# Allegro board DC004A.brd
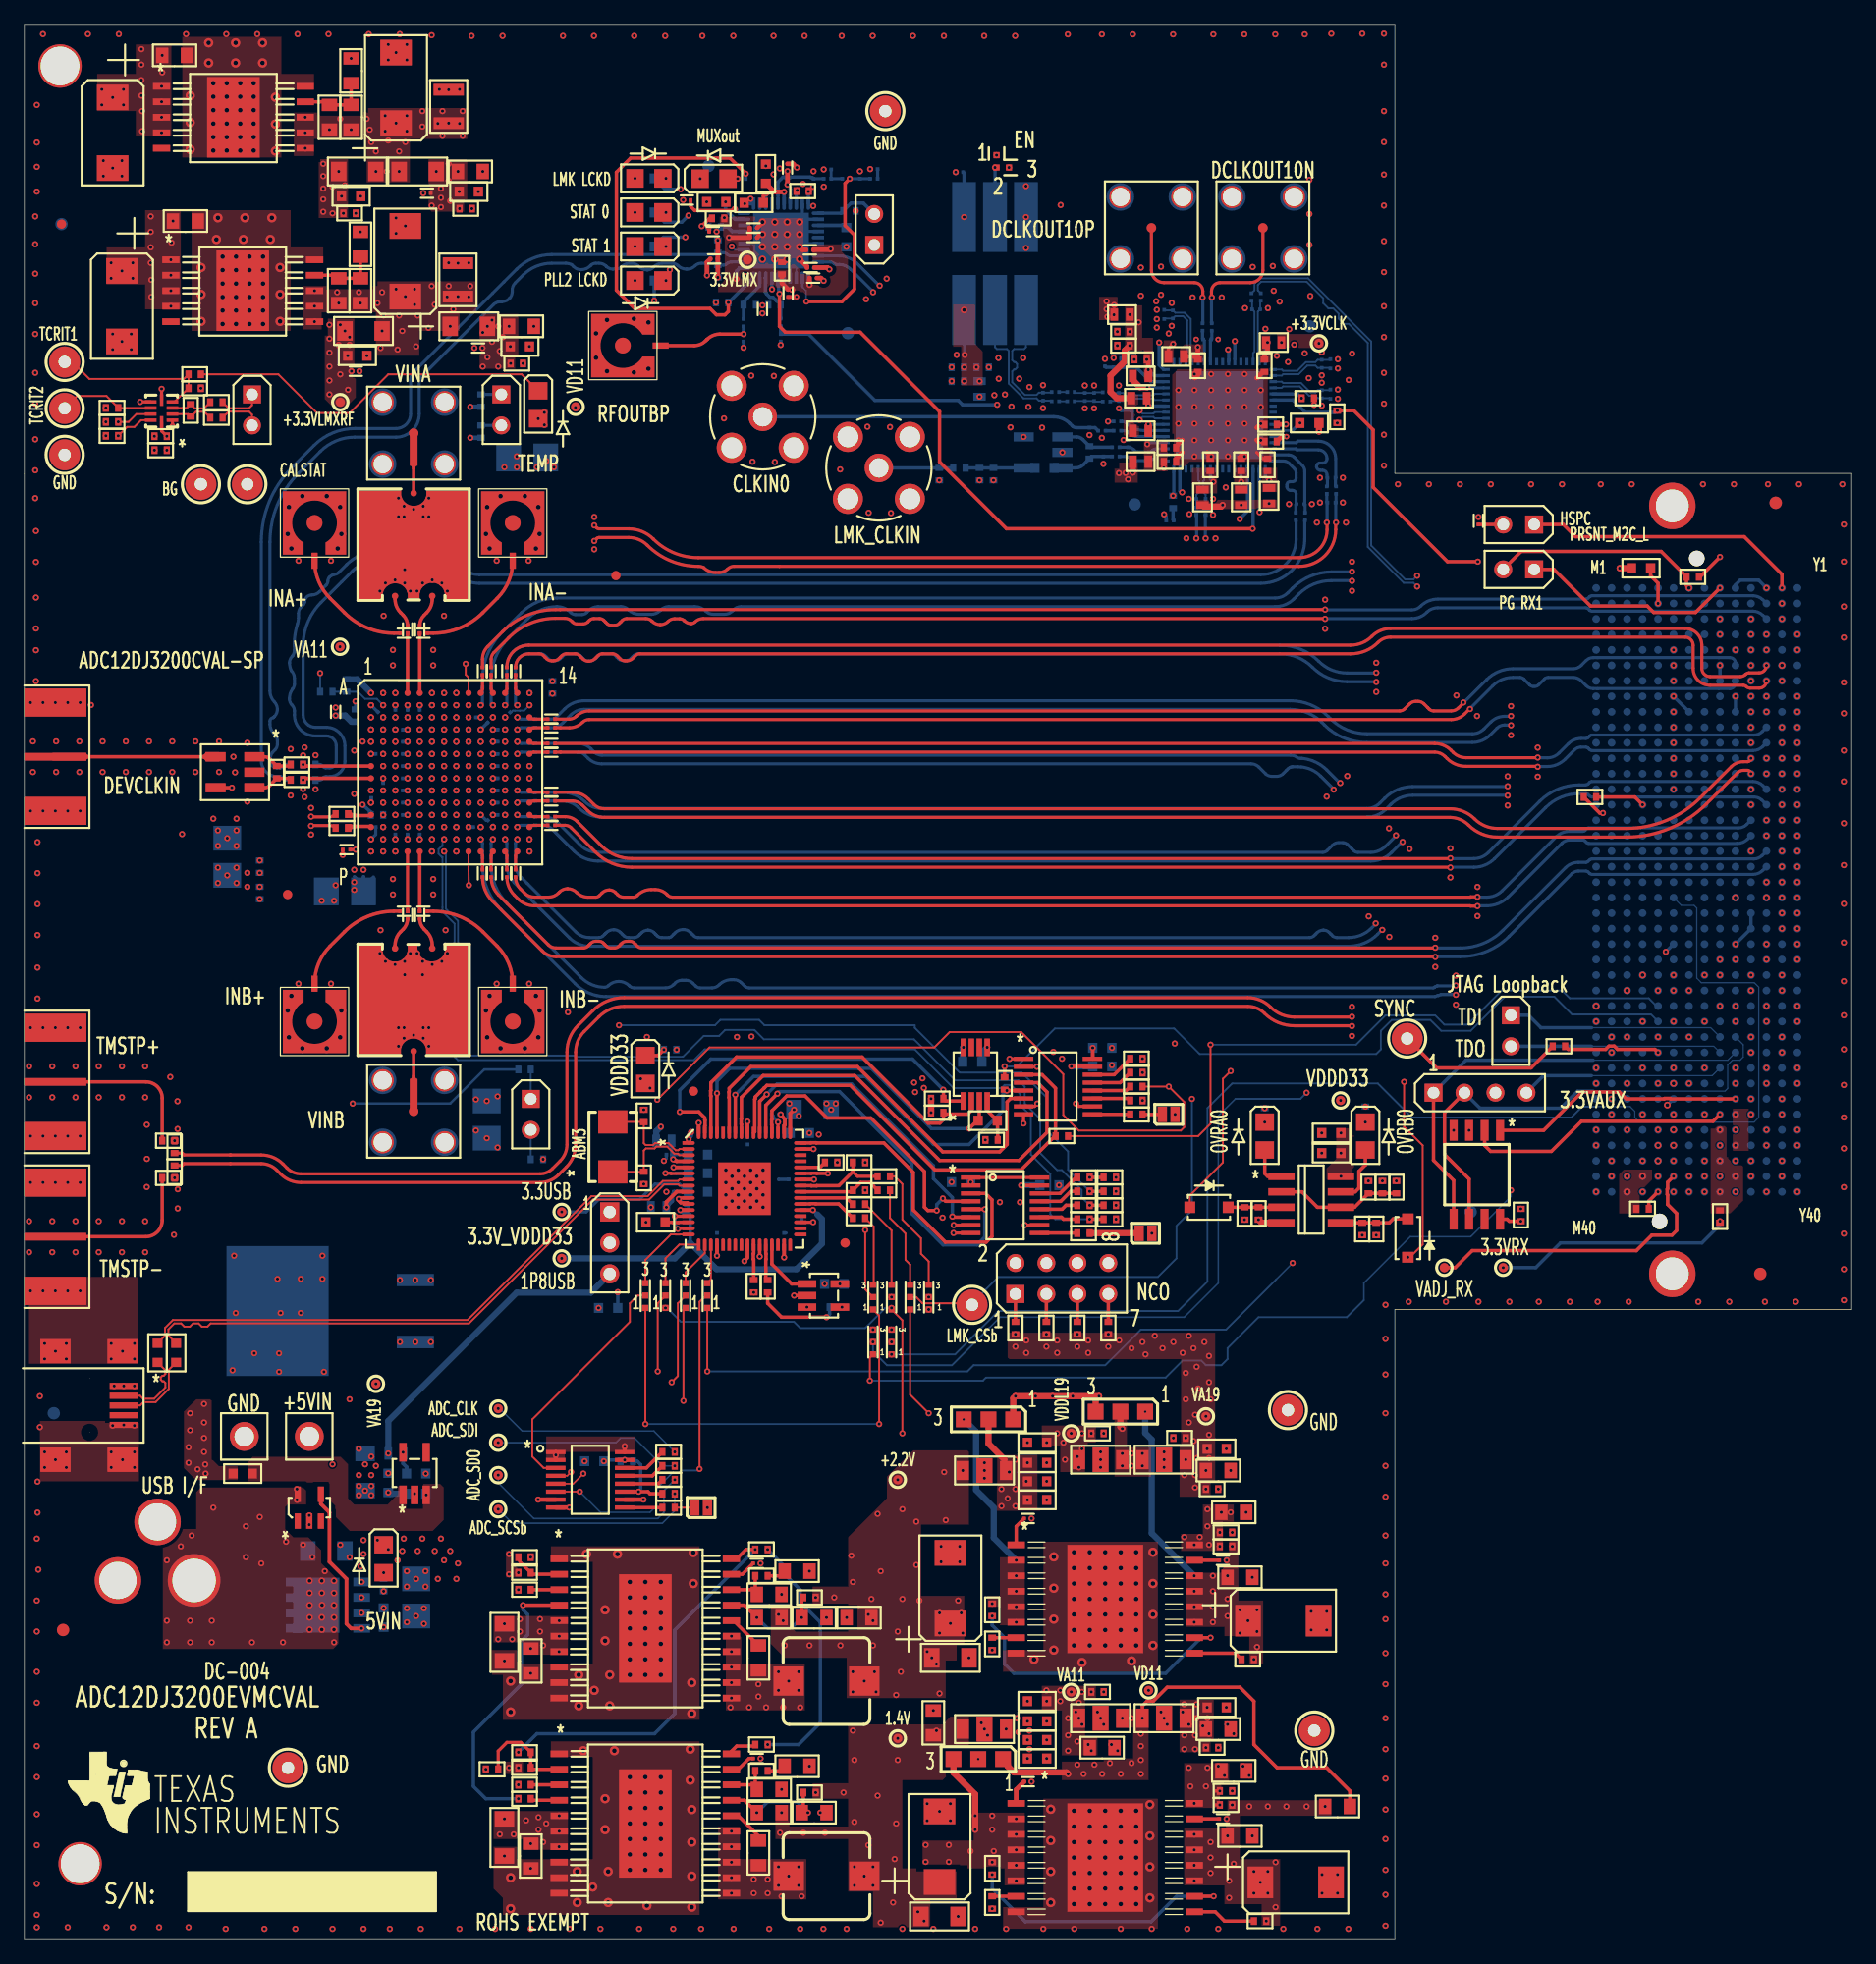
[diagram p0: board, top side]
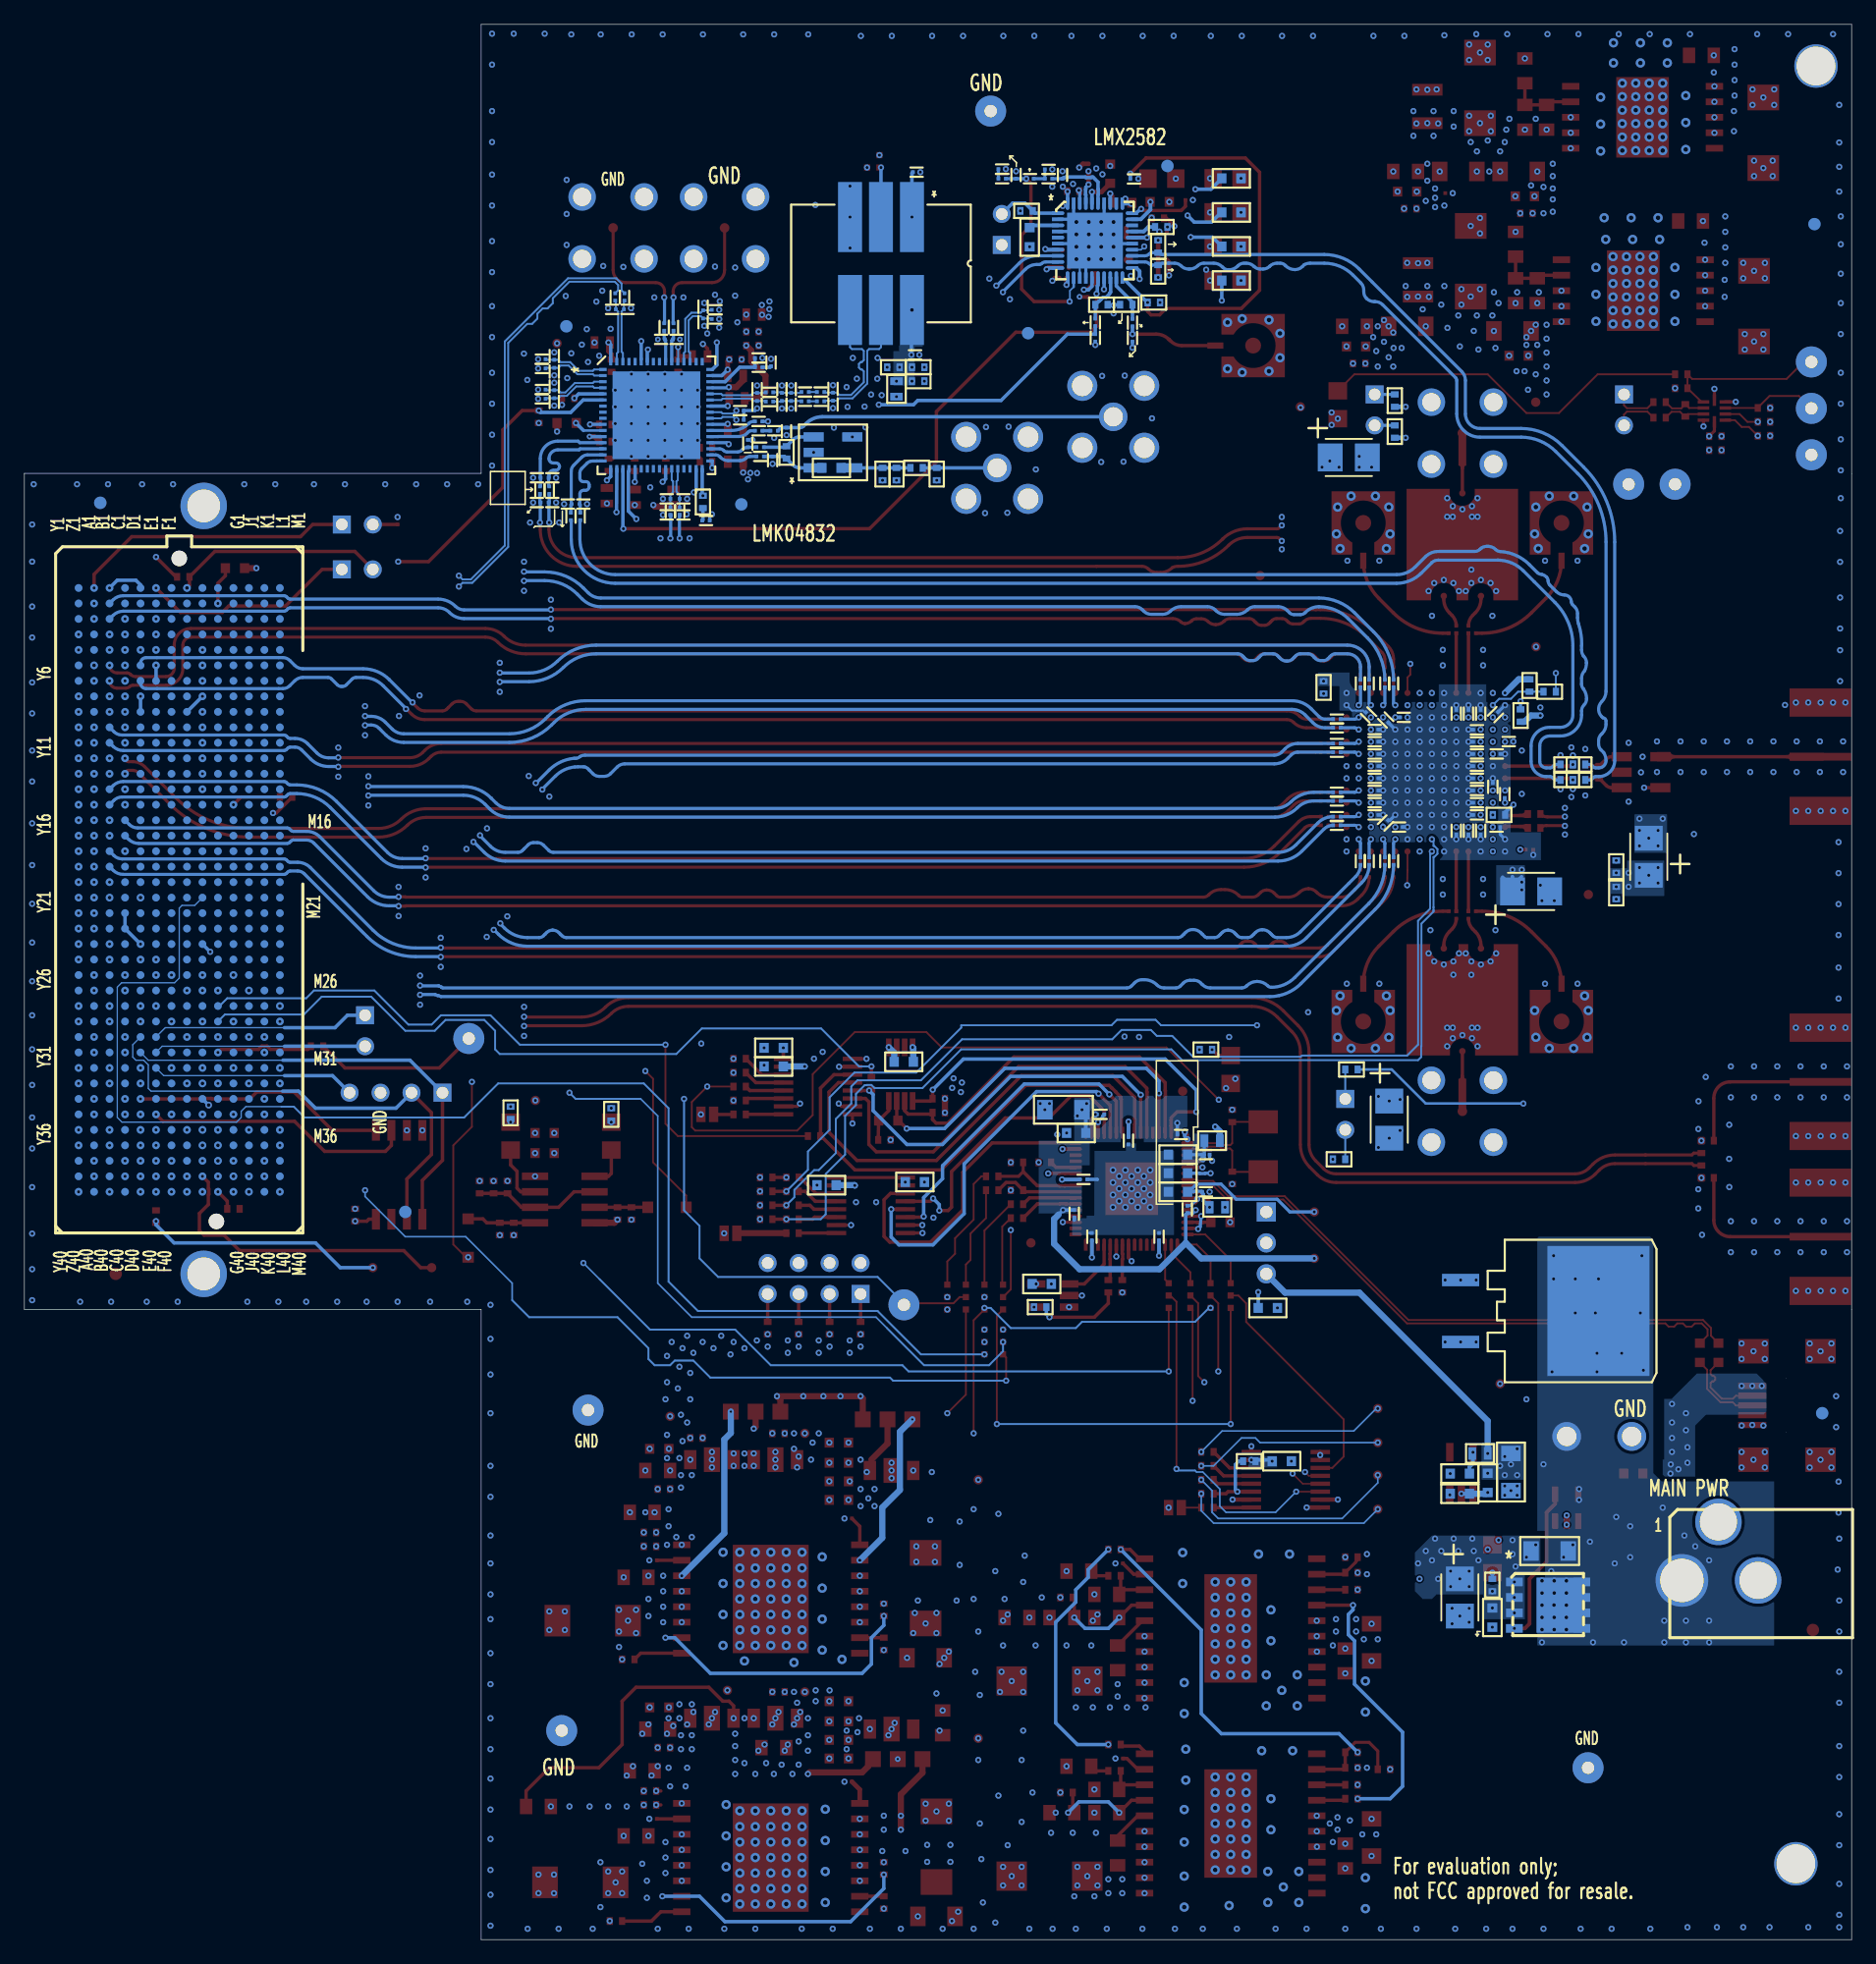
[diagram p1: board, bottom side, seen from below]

Outline 149.86 x 157.1 mm; copper layers: TOP, L02_GND-1, L03_GND-2, L04_SIG-1, L05_GND-3, L06_PWR-1, L07_GND-4, L08_PWR-2, L09_GND-5, L10_SIG-2, L11_GND-6, BOTTOM. Coordinates in mm from the lower left corner of the outline.
Outline path: 0,157.1 0,0 112.39,0 112.39,51.69 149.86,51.69 149.86,120.27 112.39,120.27 112.39,157.1 0,157.1

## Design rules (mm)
net group CLK: nets CLKM CLKP
net group CLKIN0_P_N: nets CLKIN0_N CLKIN0_P
net group CLKIN1: nets CLKIN1_N CLKIN1_P
net group CLKINN: nets CLKINN CLKINP
net group CLKLA0: nets CLKLA_0N CLKLA_0P
net group DA4: nets DA4+ DA4-
net group DA5: nets DA5+ DA5-
net group DA6: nets DA6+ DA6-
net group DA7: nets DA7+ DA7-
net group DB4: nets DB4+ DB4-
net group DB5: nets DB5+ DB5-
net group DB6: nets DB6+ DB6-
net group DB7: nets DB7+ DB7-
net group DCLKOUT2: nets DCLKOUT2_N DCLKOUT2_P
net group DCLKOUT8: nets DCLKOUT8_N DCLKOUT8_P
net group DCLKOUT102: nets DCLKOUT10_N DCLKOUT10_P
net group DIFFPAIR9: nets GTXCLKM GTXCLKP
net group DIFFPAIR10: nets N20382827 N20382847
net group DIFFPAIR11: nets INA+ INA-
net group DMP: nets DM DP
net group DP5: nets SYSREF+ SYSREF-
net group DP8: nets LMX_OSCM LMX_OSCP
net group DP17: nets JESD_SYSREFM JESD_SYSREFP
net group DP19: nets LMX_CLKM LMX_CLKP
net group FPGA_JESD_CLKC: nets FPGA_JESD_CLK_C_N FPGA_JESD_CLK_C_P
net group INAN: nets INAN INAP
net group INBN: nets INBN INBP
net group OSC: nets OSCN OSCP
net group OSC_PAIR: nets OSC_M OSC_P
net group OSCIN: nets OSCINN OSCINP
net group OSCIO: nets OSCI OSCO
net group OSCOUT: nets DCLKOUT6_N DCLKOUT6_P
net group SYNC: nets SYNC_N SYNC_P
net group SYSREF: nets SYSREFM SYSREFP
net group TDIODE: nets TDIODE+ TDIODE-
net group TMSTP: nets TMSTP+ TMSTP-
net group Y2: nets Y1_N Y1_P
net group YO1: nets YO1_N YO1_P
net group A-INPUT: nets CLK+ CLK- CLK_+ CLK_- DEVCLKIN INA_+ INA_- INB+ INB- INB_+ INB_- TMSP+ TMSP- VINA VINB
net group HS: nets DA0+ DA0- DA0_M DA0_P DA1+ DA1- DA1_M DA1_P DA2+ DA2- DA2_M DA2_P DA3+ DA3- DA3_M DA3_P DA4_M DA4_P DA5_M DA5_P DA6_M DA6_P DA7_M DA7_P DB0+ DB0- DB0_M DB0_P DB1+ DB1- DB1_M DB1_P DB2+ DB2- DB2_M DB2_P DB3+ DB3- DB3_M DB3_P DB4_M DB4_P DB5_M DB5_P DB6_M DB6_P DB7_M DB7_P
net group LENGTH: nets FPGA_JESD_CLK_A_N FPGA_JESD_CLK_A_P FPGA_JESD_CLK_B_N FPGA_JESD_CLK_B_P FPGA_JESD_SYSREFM FPGA_JESD_SYSREFP

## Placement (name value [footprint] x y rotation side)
BALUN1  BALUN, HIGH POWER, SMT  [BALUN_320X320_MARKI_0006SMG]  31.93 114.43 0 top
BALUN2  BALUN, HIGH POWER, SMT  [BALUN_320X320_MARKI_0006SMG]  31.93 77.09 180 top
C1  0.1uF  [0603]  107.19 66.17 180 top
C2  1uF  [0603]  107.19 64.52 180 top
C3  .1uF  [0402]  101.22 59.56 90 top
C4  .1uF  [0402]  111.38 61.72 270 top
C5  .1uF  [0201]  43.22 98.11 0 top
C6  .1uF  [0201]  43.22 97.4 0 top
C7  .1uF  [0201]  43.22 100.11 0 top
C8  .1uF  [0201]  43.22 99.4 0 top
C9  .1uF  [0201]  39.57 104.05 90 top
C10  .1uF  [0201]  40.28 104.05 90 top
C11  .1uF  [0201]  37.57 104.05 90 top
C12  .1uF  [0201]  38.28 104.05 90 top
C13  .1uF  [0201]  42.22 98.11 0 bottom
C14  .1uF  [0402]  109.73 58.29 90 top
C15  .1uF  [0201]  42.22 97.4 0 bottom
C16  .1uF  [0201]  42.22 100.11 0 bottom
C17  10uF  [0603]  83.06 17.91 0 top
C18  .1uF  [0201]  42.22 99.4 0 bottom
C19  .1uF  [0201]  39.57 103.03 90 bottom
C20  .1uF  [0201]  89.64 123.77 0 bottom
C21  .1uF  [0201]  40.28 103.03 90 bottom
C22  .1uF  [0201]  37.57 103.03 90 bottom
C23  .1uF  [0201]  38.28 103.03 90 bottom
C24  .1uF  [0201]  89.64 124.53 0 bottom
C25  .1uF  [0201]  43.22 93.4 0 top
C26  .1uF  [0201]  43.22 94.11 0 top
C27  .1uF  [0201]  43.22 91.4 0 top
C28  .1uF  [0201]  43.22 92.11 0 top
C29  .1uF  [0201]  39.57 87.46 270 top
C30  .1uF  [0201]  40.28 87.46 270 top
C31  .1uF  [0201]  37.57 87.46 270 top
C32  .1uF  [0201]  38.28 87.46 270 top
C33  .1uF  [0201]  42.22 93.4 0 bottom
C34  .1uF  [0201]  42.22 94.11 0 bottom
C35  .1uF  [0201]  42.22 91.4 0 bottom
C36  .1uF  [0201]  42.22 92.11 0 bottom
C37  .1uF  [0201]  39.57 88.46 270 bottom
C38  .1uF  [0201]  40.28 88.46 270 bottom
C39  .1uF  [0201]  37.57 88.46 270 bottom
C40  .1uF  [0201]  38.28 88.46 270 bottom
C41  100pF  [0402]  11.18 123.32 180 top
C42  .1uF  [0402]  11.18 122.17 180 top
C43  10uF  [TANT_B]  41.24 121.57 180 bottom
C44  100pF  [0402]  13.64 125.44 90 top
C45  .1uF  [0402]  26.04 92.33 0 top
C47  .1uF  [0402]  26.04 91.19 0 top
C48  4700pF  [0402]  23.37 96.39 180 bottom
C49  4700pF  [0402]  22.35 96.39 0 top
C50  4700pF  [0402]  22.35 96.39 0 bottom
C51  4700pF  [0402]  22.35 95.12 0 bottom
C52  4700pF  [0402]  22.35 95.13 0 top
C53  4700pF  [0402]  23.37 95.12 180 bottom
C54  .1uF  [0201]  30.73 99.24 0 bottom
C55  .1uF  [0201]  30.73 98.25 0 bottom
C56  .1uF  [0201]  30.73 97.26 0 bottom
C57  .1uF  [0201]  29.11 97.26 180 bottom
C58  .1uF  [0201]  29.42 94.56 90 bottom
C59  .1uF  [0201]  30.73 96.26 0 bottom
C60  .1uF  [0201]  30.73 92.26 0 bottom
C61  .1uF  [0201]  30.73 93.26 0 bottom
C62  .1uF  [0201]  30.73 95.26 0 bottom
C63  .1uF  [0201]  30.73 94.26 0 bottom
C64  .1uF  [0201]  39.12 93.26 180 bottom
C65  .1uF  [0201]  39.12 94.26 180 bottom
C66  1uF  [0402]  19.3 85.85 270 bottom
C67  1uF  [0402]  19.3 88.01 90 bottom
C68  10uF  [TANT_B]  16.64 88.82 90 bottom
C69  .1uF  [0201]  29.21 100.48 135 bottom
C70  .1uF  [0201]  28.45 93.95 90 bottom
C71  .1uF  [0201]  29.12 91.26 180 bottom
C72  .1uF  [0201]  28.12 98.27 180 bottom
C73  .1uF  [0201]  32.43 100.56 90 bottom
C74  .1uF  [0201]  31.43 100.56 90 bottom
C75  .1uF  [0201]  30.43 100.56 90 bottom
C76  .1uF  [0201]  25.53 100.71 90 top
C77  .1uF  [0201]  26.42 89.41 180 top
C78  .1uF  [0201]  32.43 90.95 270 bottom
C79  .1uF  [0201]  31.43 90.95 270 bottom
C80  .1uF  [0201]  30.43 90.95 270 bottom
C81  1uF  [0402]  27.15 100.41 90 bottom
C82  1uF  [0402]  28.92 92.26 180 bottom
C83  10uF  [TANT_B]  26.29 85.98 180 bottom
C84  .1uF  [0201]  36.73 100.26 180 bottom
C85  .1uF  [0201]  39.12 99.26 180 bottom
C86  .1uF  [0201]  39.12 98.26 180 bottom
C87  .1uF  [0201]  39.12 97.25 180 bottom
C88  .1uF  [0201]  39.12 96.26 180 bottom
C89  .1uF  [0201]  38.21 100.04 225 bottom
C90  .1uF  [0201]  39.62 100.46 45 bottom
C91  .1uF  [0201]  37.12 91.26 180 bottom
C92  .1uF  [0201]  39.12 92.26 180 bottom
C93  .1uF  [0201]  38.23 91.59 135 bottom
C94  1uF  [0402]  43.31 102.72 90 bottom
C95  10uF  [TANT_B]  37.92 67.26 270 bottom
C96  .1uF  [0201]  39.12 95.26 180 bottom
C99  100pF  [0201]  56.57 137.87 180 top
C100  .1uF  [0201]  64.42 138.6 180 top
C101  .1uF  [0201]  59.79 139.61 0 top
C102  1uF  [0402]  62.13 137.1 270 top
C103  .1uF  [0201]  64.7 136.29 0 top
C104  .1uF  [0201]  64.49 137.15 0 top
C105  100pF  [0201]  60.53 133.75 270 top
C106  .1uF  [0201]  62.64 135.05 270 top
C107  .1uF  [0201]  62.59 145.36 270 top
C108  100pF  [0201]  62.03 132.66 270 bottom
C109  .1uF  [0201]  56.47 140.1 180 top
C110  100pF  [0201]  58.98 132.63 270 bottom
C111  1uF  [0402]  56.62 140.48 0 bottom
C112  10uF  [0603]  56.75 142.54 0 top
C113  .1uF  [0201]  59.79 140.41 0 top
C114  1uF  [0402]  56.9 141.19 0 top
C115  10uF  [0603]  60.81 144.85 270 top
C116  10uF  [0603]  67.41 139.64 90 bottom
C117  1uF  [0402]  63.83 143.43 180 top
C118  10uF  [0603]  59.82 142.46 0 top
C119  560pF  [0201]  68.53 144.75 90 bottom
C120  .047uF  [0201]  69.67 144.44 0 bottom
C121  6800pF  [0201]  65.86 145.2 180 bottom
C122  6800pF  [0201]  64.72 144.75 90 bottom
C123  10uF  [0603]  83.06 16.38 0 top
C124  10uF  [0603]  83.06 39.12 0 top
C125  10uF  [0603]  83.06 37.59 0 top
C126  10uF  [0603]  83.06 36.07 0 top
C127  .1uF  [0805]  99.7 29.72 0 top
C128  .68uF  [0402]  94.21 117.93 270 bottom
C129  10uF  [0603]  83.06 14.86 0 top
C130  .1uF  [0201]  76.68 144.98 180 bottom
C131  3900pF  [0201]  89.64 128.98 180 bottom
C132  47pF  [0201]  89.64 129.74 180 bottom
C133  .1uF  [0201]  105.04 116.74 270 bottom
C134  .01uF  [0201]  89.51 121.66 0 bottom
C135  .1uF  [0201]  104.27 116.74 270 bottom
C136  .01uF  [0201]  89.51 122.42 0 bottom
C137  .1uF  [0201]  90.53 122.71 270 bottom
C138  .1uF  [0201]  76.81 129.99 0 bottom
C139  100pF  [0402]  76.56 128.98 0 bottom
C140  2200pF  [0402]  78.59 128.98 180 bottom
C141  10pF  [0402]  76.56 127.83 0 bottom
C142  .1uF  [0201]  96.62 132.28 90 bottom
C143  .1uF  [0201]  97.39 132.28 90 bottom
C144  .1uF  [0201]  85.83 126.18 0 bottom
C145  .1uF  [0201]  88.75 126.16 0 bottom
C146  .1uF  [0201]  89.77 125.9 90 bottom
C149  .1uF  [0201]  85.83 126.94 0 bottom
C150  .1uF  [0201]  88.75 126.92 0 bottom
C151  .1uF  [0201]  96.88 117.16 270 bottom
C152  12pF  [0201]  89.77 127.17 270 bottom
C153  .1uF  [0201]  96.12 117.16 270 bottom
C154  1uF  [0402]  102.21 124.28 0 top
C155  .1uF  [0402]  93.96 121.23 180 top
C156  0.01uF  [0402]  93.96 122.37 180 top
C157  1uF  [0402]  101.96 120.97 90 top
C158  1uF  [0402]  99.8 120.97 90 top
C159  1uF  [0402]  97.26 120.97 90 top
C160  1uF  [0402]  90.15 131.9 0 top
C161  .1uF  [0402]  90.15 130.75 0 top
C162  0.01uF  [0402]  91.54 129.61 0 top
C163  .1uF  [0402]  102.21 122.88 180 top
C164  10uF  [0603]  105.39 124.4 0 top
C165  1uF  [0402]  96.24 129.1 270 top
C166  1uF  [0402]  101.7 129.1 270 top
C167  1uF  [0402]  122.73 59.44 270 top
C168  10uF  [0603]  55.25 64.39 0 bottom
C169  .1uF  [0201]  52.96 64.39 180 bottom
C170  10uF  [0603]  55.25 61.34 0 bottom
C171  .1uF  [0201]  52.96 61.34 180 bottom
C172  0.1uF  [0603]  66.42 53.78 180 bottom
C173  1uF  [0603]  32.13 38.23 0 bottom
C174  100uF  [1206]  27.94 38.35 270 bottom
C175  1uF  [0603]  32.13 36.58 180 bottom
C176  .1uF  [0201]  61.6 67.69 180 bottom
C177  0.1uF  [0603]  29.84 37.47 270 bottom
C178  100uF  [1206]  64.64 68.07 0 bottom
C179  10uF  [0603]  63.6 66.17 0 bottom
C180  1uF  [0603]  77.74 72 0 bottom
C181  .1uF  [0201]  54.99 66.04 180 bottom
C182  .1uF  [0201]  54.48 59.89 90 bottom
C183  .1uF  [0201]  63.75 59.54 270 bottom
C184  18pF  [0402]  50.8 67.56 90 top
C185  18pF  [0402]  50.8 62.48 270 top
C186  .1uF  [0201]  56.8 57.66 90 bottom
C187  .1uF  [0201]  62.99 62.36 180 bottom
C188  .1uF  [0201]  62.31 57.66 90 bottom
C189  .1uF  [0201]  59.31 65.53 270 bottom
C190  0.1uF  [0603]  47.88 51.82 180 bottom
C191  0.1uF  [0603]  46.74 39.24 180 bottom
C192  0.1uF  [0603]  76.83 62.14 180 bottom
C193  0.1uF  [0603]  84.07 61.89 0 bottom
C194  0.1uF  [0603]  88.4 73.15 0 bottom
C195  0.1uF  [0603]  88.4 71.62 0 bottom
C196  47uF  [TANT_B]  32.13 28.07 270 bottom
C198  10uF  [0603]  29.46 26.42 270 bottom
C200  10uF  [0603]  83.06 40.77 180 top
C201  1uF  [0402]  88.01 41.53 0 top
C202  10uF  [0603]  97.79 40.26 0 top
C203  .1uF  [0402]  94.74 41.15 180 top
C204  33uF  [0805]  97.92 38.48 0 top
C205  1uF  [0402]  97.41 36.96 0 top
C206  220uF  [TANT_D]  103.25 26.16 0 top
C207  1000pF  [0805]  99.19 35.05 0 top
C208  330uF  [TANT_D]  75.95 28.83 90 top
C209  .1uF  [0805]  68.45 26.42 180 top
C210  10000pF  [0201]  98.3 31.11 0 top
C211  2200pF  [0201]  82.3 34.54 0 top
C212  47uF  [1206]  75.95 23.11 0 top
C213  22uF  [1206]  39.37 24.38 270 top
C214  10uF  [0805]  41.53 22.86 270 top
C215  12nF  [0201]  60.07 30.86 0 top
C216  91pF  [0805]  61.09 28.32 0 top
C217  270pF  [0805]  61.09 26.42 180 top
C218  33uF  [0805]  88.39 15.75 0 top
C219  10uF  [0603]  83.06 19.56 180 top
C220  1uF  [0402]  88.01 20.32 0 top
C221  .1uF  [0805]  60.2 23.11 270 top
C222  33uF  [0805]  97.92 17.27 0 top
C223  10uF  [0603]  97.79 19.05 0 top
C224  1uF  [0402]  97.41 15.75 0 top
C225  .027uF  [0805]  63.37 30.23 0 top
C226  1000pF  [0805]  99.19 13.84 0 top
C227  330uF  [TANT_D]  75.06 7.62 90 top
C228  220uF  [TANT_D]  104.27 4.7 0 top
C229  33uF  [0805]  36.58 145.03 0 top
C230  10uF  [0603]  36.45 143.38 0 top
C231  .1uF  [0805]  99.7 8.51 0 top
C232  .1uF  [0805]  74.55 17.78 90 top
C233  .1uF  [0402]  36.2 141.99 0 top
C234  .01uF  [0201]  33.02 143.26 180 top
C236  10uF  [0603]  26.8 143 0 top
C237  .1uF  [0402]  26.67 141.61 0 top
C242  33uF  [0805]  40.77 132.33 0 top
C243  10uF  [0603]  40.64 130.68 0 top
C244  .1uF  [0402]  40.39 129.29 0 top
C245  .01uF  [0201]  37.21 130.56 180 top
C247  10uF  [0603]  27.3 129.92 0 top
C248  .01uF  [0201]  27.18 128.65 0 top
C249  .1uF  [0201]  97.18 116.86 0 bottom
C250  .1uF  [0201]  95.81 116.86 180 bottom
C251  .1uF  [0805]  60.2 7.11 270 top
C254  270pF  [0805]  61.09 10.41 180 top
C255  22uF  [1206]  39.37 8.38 270 top
C256  10uF  [0805]  41.53 6.86 270 top
C258  12nF  [0201]  60.07 14.86 0 top
C259  1uF  [0805]  12.32 154.56 0 top
C260  15uF  [TANT_X]  7.24 148.21 270 top
C261  470pF  [0805]  25.02 149.48 90 top
C262  22uF  [TANT_D]  30.48 151.89 90 top
C263  .1uF  [1210]  34.8 150.37 90 top
C264  1uF  [0805]  13.21 140.97 0 top
C265  15uF  [TANT_X]  8 133.99 270 top
C266  470pF  [0805]  25.78 135.26 90 top
C267  22uF  [TANT_D]  31.24 137.67 90 top
C268  .1uF  [1210]  35.56 136.14 90 top
C269  .027uF  [0805]  63.37 14.22 0 top
C270  47uF  [1206]  75.06 1.91 0 top
C271  150pF  [0805]  61.09 12.32 0 top
C272  2200pF  [0201]  82.3 12.95 0 top
C273  10000pF  [0201]  98.3 9.91 0 top
D1  LED RED  [LED_0805]  42.14 125.9 90 top
D2  LED GREEN  [LED_0805]  56.57 144.44 180 top
D3  LED GREEN  [LED_0805]  51.22 141.68 0 top
D4  LED GREEN  [LED_0805]  51.22 138.88 0 top
D5  LED GREEN  [LED_0805]  51.22 144.47 0 top
D6  LED GREEN  [LED_0805]  51.22 136.09 0 top
D7  LED GREEN  [LED_0805]  50.93 71.37 90 top
D8  LED GREEN  [LED_0805]  29.46 31.24 90 top
D9  1N4148W  [DIODE_SM_1N4148W]  113.46 57.55 90 top
D10  LED ORANGE  [LED_0805]  109.98 65.91 90 top
D11  LED ORANGE  [LED_0805]  101.73 65.91 90 top
D12  1N4148W  [DIODE_SM_1N4148W]  97.16 60.07 0 top
D13  MBRB2515L  [DIODE_MBRB2515L]  26.42 51.56 0 bottom
F1  FUSE 10A 63V FAST  [1206]  24.77 31.88 0 bottom
FB1  120 OHM @ 100MHz  [IND_0603]  78.34 127.2 270 bottom
FB2  120 OHM @ 100MHz  [IND_0603]  91.54 121.23 0 top
FB3  120 OHM @ 100MHz  [IND_0603]  102.08 118.43 90 top
FB4  120 OHM @ 100MHz  [IND_0603]  99.8 118.31 90 top
FB5  120 OHM @ 100MHz  [IND_0603]  96.62 118.31 90 top
FB6  120 OHM @ 100MHz  [IND_0603]  90.02 133.29 0 top
FB7  120 OHM @ 100MHz  [IND_0603]  91.54 123.77 0 top
FB8  120 OHM @ 100MHz  [IND_0603]  91.42 126.44 0 top
FB9  120 OHM @ 100MHz  [IND_0603]  91.54 128.26 180 top
FB10  120 OHM @ 100MHz  [IND_0603]  94.46 129.86 0 top
FB11  120 OHM @ 100MHz  [IND_0603]  102.47 131.01 180 top
FB12  120 OHM @ 100MHz  [IND_0603]  52.45 65.53 0 bottom
FB13  120 OHM @ 100MHz  [IND_0603]  52.02 60.07 0 bottom
FB14  26 OHM @ 100MHz  [IND_0603]  30.48 39.88 180 bottom
FB16  27uF  [1206_BEAD_NFM31P]  88.27 39.37 180 top
FB17  27uF  [1206_BEAD_NFM31P]  93.47 39.37 0 top
FB18  27uF  [1206_BEAD_NFM31P]  88.27 18.16 180 top
FB19  27uF  [1206_BEAD_NFM31P]  93.47 18.16 0 top
FB20  120 OHM @ 100MHz  [1206]  32.26 145.03 0 top
FB21  120 OHM @ 100MHz  [1206]  27.3 145.03 180 top
FB22  120 OHM @ 100MHz  [1206]  36.45 132.33 0 top
FB23  120 OHM @ 100MHz  [1206]  27.81 131.95 180 top
FB24  27uF  [1206_BEAD_NFM31P]  78.74 38.48 0 top
FB25  27uF  [1206_BEAD_NFM31P]  78.74 17.27 0 top
J1  SMP, PCB, SMT  [SMP_B120]  23.8 116.2 0 top
J2  SMA, THVT, SMT CENTER PIN  [SMA_THVT_SMT_250X250]  31.93 123.57 90 top
J3  SMP, PCB, SMT  [SMP_B120]  40.05 116.2 0 top
J4  SMP, PCB, SMT  [SMP_B120]  23.8 75.31 180 top
J5  SMA, THVT, SMT CENTER PIN  [SMA_THVT_SMT_250X250]  31.93 67.95 270 top
J6  SMP, PCB, SMT  [SMP_B120]  40.05 75.31 180 top
J7  HDR, THVT, 8POS, .100, GOLD  [HDR_THVT_2X4_100_M]  81.28 52.96 90 top
J8  HDR, THVT, 2POS, .100, GOLD  [HDR_THVT_1X2_100_M]  41.53 68.96 0 top
J9  HDR, THVT, 2POS, .100, GOLD  [HDR_THVT_1X2_100_M]  39.12 126.75 0 top
J14  SMA, JACK, 50 OHM, EDGE MNT  [SMA_SMEL_373X312]  0 70.36 90 top
J15  SMA, JACK, 50 OHM, EDGE MNT  [SMA_SMEL_373X312]  0 57.66 90 top
J17  HDR, THVT, 2POS, .100, GOLD  [HDR_THVT_1X2_100_M]  18.67 126.75 0 top
J18  SMA, JACK, 50 OHM, EDGE MNT  [SMA_SMEL_373X312]  0 97.03 90 top
J20  SMP, PCB, SMT  [SMP_B120]  49.08 130.75 90 top
J22  SMA_THVT_REC  [SMA_THVT_312X312]  70.08 120.72 0 top
J23  SMA, THVT, SMT CENTER PIN  [SMA_THVT_SMT_250X250]  92.43 140.41 0 top
J24  SMA, THVT, SMT CENTER PIN  [SMA_THVT_SMT_250X250]  101.58 140.41 0 top
J25  CON, SMVT, HS, FIELD ARRAY, FMC, MALE  [CON_SMVT_40X14_50_M_MTG]  137.16 86.11 90 bottom
J26  HDR, THVT, 2POS, .100, GOLD  [HDR_THVT_1X2_100_M]  123.83 112.39 270 top
J27  HDR, THVT, 2POS, .100, GOLD  [HDR_THVT_1X2_100_M]  121.92 75.82 0 top
J28  HDR, THVT, 4POS, .100, GOLD  [HDR_THVT_1X4_100_M]  115.57 69.47 90 top
J30  HDR, THVT, 2POS, .100, GOLD  [HDR_THVT_1X2_100_M]  123.83 116.08 270 top
J31  CON, USB, MINI, AB, SMT  [CON_SMRT_USBMNE20_F]  4.7 43.81 0 top
J37  CONN, JACK, PWR, MINI, R/A, TH  [CON_RAPC722_JACK_THVT_3]  10.79 29.46 90 bottom
J38  SMA_THVT_REC  [SMA_THVT_312X312]  60.56 124.91 0 top
JP5  HDR, THVT, 2POS, .100, GOLD  [HDR_THVT_1X2_100_M]  69.7 139.01 180 top
JP6  HDR, THVT, 3POS, .100, GOLD  [HDR_THVT_1X3_100_M]  48.01 59.69 0 top
L6  1.5uH  [IND_SM_6P7MMX6P7MM]  65.79 5.21 0 top
L7  1.5uH  [IND_SM_6P7MMX6P7MM]  65.79 21.21 0 top
MT1  STANDOFF, FEMALE, 4-40 X 1 3/16", AL  [MFG125_PLATED]  4.57 6.22 0 top
MT2  STANDOFF, FEMALE, 4-40 X 1 3/16", AL  [MFG125_PLATED]  2.92 153.68 0 top
NOREF  -  [unnamed]  143.64 117.86 0 top
NOREF#2  -  [#2]  142.88 89.28 270 top
NOREF#3  -  [#2]  141.6 95.63 0 top
NOREF#4  -  [#2]  22.86 95.76 90 top
NOREF#5  -  [#2]  142.88 99.44 270 top
NOREF#6  -  [#2]  41.18 114.88 90 top
NOREF#7  -  [#2]  117.41 77.88 90 top
NOREF#8  -  [#2]  101.58 140.41 0 top
NOREF#9  -  [#2]  10.41 102.11 0 top
NOREF#10  -  [#2]  69.88 135.4 45 top
NOREF#11  -  [#2]  92.43 140.41 0 top
NOREF#12  -  [unnamed]  142.37 54.61 0 top
NOREF#13  -  [#2]  25.42 92.54 90 top
NOREF#14  -  [#2]  96.5 114.94 0 top
NOREF#15  -  [#2]  119.17 85.16 90 top
NOREF#16  -  [#2]  149.86 51.69 90 top
NOREF#17  -  [#2]  106.68 108.72 90 top
NOREF#18  -  [unnamed#3]  48.51 111.89 0 top
NOREF#19  -  [#2]  2.54 57.66 0 top
NOREF#20  -  [#2]  118.29 101.21 135 top
NOREF#21  -  [#2]  145.41 89.28 0 top
NOREF#22  -  [#2]  144.15 91.82 0 top
NOREF#23  -  [#2]  110.87 103.54 90 top
NOREF#24  -  [#2]  141.6 100.71 0 top
NOREF#25  -  [#2]  238.12 63.12 0 top
NOREF#26  -  [#2]  112.39 120.27 90 top
NOREF#27  -  [#2]  140.34 104.52 270 top
NOREF#28  -  [#2]  107.19 116.24 0 top
NOREF#29  -  [#2]  14.07 111.65 0 top
NOREF#30  -  [#2]  142.88 103.25 0 top
NOREF#31  -  [#2]  121.65 94.22 90 top
NOREF#32  -  [#2]  108.88 111.83 90 top
NOREF#33  -  [#2]  141.6 91.82 270 top
NOREF#34  -  [#2]  142.88 109.6 270 top
NOREF#35  -  [#2]  145.41 94.36 0 top
NOREF#36  -  [#2]  0 0 90 top
NOREF#37  -  [#2]  112.39 0 90 top
NOREF#38  -  [#2]  0 157.1 0 top
NOREF#39  -  [#2]  70.08 120.72 0 top
NOREF#40  -  [#2]  145.41 93.09 0 top
NOREF#41  -  [unnamed#3]  54.86 69.6 0 top
NOREF#42  -  [#2]  115.71 80.99 90 top
NOREF#43  -  [unnamed]  3.17 25.4 0 top
NOREF#44  -  [#2]  60.56 124.91 0 top
NOREF#45  -  [#2]  121.92 99.99 90 top
NOREF#46  -  [#2]  142.88 94.36 270 top
NOREF#47  -  [#2]  36.12 99.36 0 top
NOREF#48  -  [#2]  145.41 99.44 0 top
NOREF#49  -  [#2]  3.57 8.72 0 top
NOREF#50  -  [#2]  141.6 101.98 0 top
NOREF#51  -  [#2]  144.15 90.55 0 top
NOREF#52  -  [#2]  6.45 2.98 0 top
NOREF#53  -  [#2]  111.1 83.09 135 top
NOREF#54  -  [#2]  145.41 84.2 0 top
NOREF#55  -  [unnamed#3]  21.59 85.72 0 top
NOREF#56  -  [#2]  -99.82 376.96 0 top
NOREF#57  -  [#2]  141.6 107.06 0 top
NOREF#58  -  [#2]  141.6 105.79 0 top
NOREF#59  -  [#2]  -110.52 -97.54 0 top
NOREF#60  -  [#2]  145.41 88.01 0 top
NOREF#61  -  [unnamed#3]  3.05 140.72 0 top
NOREF#62  -  [#2]  0 0 0 top
NOREF#63  -  [#2]  11.83 16.45 0 top
NOREF#64  -  [#2]  142.88 104.52 0 top
NOREF#65  -  [#2]  124.12 96.58 90 top
NOREF#66  -  [#2]  145.41 98.17 0 top
NOREF#67  -  [#2]  144.15 96.9 0 top
NOREF#68  -  [#2]  2.1 18.99 0 top
NOREF#69  -  [#2]  141.6 96.9 0 top
NOREF#70  -  [#2]  107.65 94.6 45 top
NOREF#71  -  [#2]  108.88 75.32 90 top
NOREF#72  -  [#2]  116.96 88.32 90 top
NOREF#73  -  [#2]  36.12 92.16 0 top
NOREF#74  -  [#2]  112.76 90.31 135 top
NOREF#75  -  [#2]  97.01 134.7 180 top
NOREF#76  -  [unnamed#3]  67.31 57.15 0 top
NOREF#77  -  [#2]  2.54 70.36 0 top
NOREF#78  -  [#2]  145.41 82.93 0 top
NOREF#79  -  [#2]  144.15 95.63 0 top
NOREF#80  -  [#2]  105.04 116.74 90 bottom
NOREF#81  -  [#2]  104.27 116.74 90 bottom
NOREF#82  -  [#2]  105.29 117.75 180 bottom
NOREF#83  -  [#2]  148.56 6.95 180 bottom
NOREF#84  -  [unnamed]  118.62 59.69 180 bottom
NOREF#85  -  [#2]  104.02 117.75 180 bottom
NOREF#86  -  [unnamed]  56.11 145.49 180 bottom
NOREF#87  -  [unnamed]  67.54 131.77 180 bottom
NOREF#88  -  [unnamed]  105.41 132.33 180 bottom
NOREF#89  -  [unnamed]  91.06 117.73 180 bottom
NOREF#90  -  [unnamed]  2.41 43.18 180 bottom
NOREF#91  -  [unnamed]  143.64 117.86 180 bottom
NOREF#92  -  [unnamed]  3.05 140.72 180 bottom
PP1  PROBE POINT  [PROBE_POINT_30PAD]  38.86 43.56 0 top
PP2  PROBE POINT  [PROBE_POINT_30PAD]  38.86 40.77 0 top
PP3  PROBE POINT  [PROBE_POINT_30PAD]  38.86 38.1 0 top
PP4  PROBE POINT  [PROBE_POINT_30PAD]  38.86 35.31 0 top
PP5  PROBE POINT  [PROBE_POINT_30PAD]  106.17 130.94 0 top
PP6  PROBE POINT  [PROBE_POINT_30PAD]  107.95 68.83 0 top
PP7  PROBE POINT  [PROBE_POINT_30PAD]  59.31 137.8 0 top
PP8  PROBE POINT  [PROBE_POINT_30PAD]  25.91 126.11 0 top
PP9  PROBE POINT  [PROBE_POINT_30PAD]  85.85 20.32 0 top
PP10  PROBE POINT  [PROBE_POINT_30PAD]  92.2 20.45 0 top
PP11  PROBE POINT  [PROBE_POINT_30PAD]  71.63 16.51 0 top
PP12  PROBE POINT  [PROBE_POINT_30PAD]  71.63 37.72 0 top
PP13  PROBE POINT  [PROBE_POINT_30PAD]  85.85 41.53 0 top
PP14  PROBE POINT  [PROBE_POINT_30PAD]  96.9 42.93 0 top
PP15  PROBE POINT  [PROBE_POINT_30PAD]  44.07 59.69 0 top
PP16  PROBE POINT  [PROBE_POINT_30PAD]  44.07 55.88 0 top
PP17  PROBE POINT  [PROBE_POINT_30PAD]  116.46 55.12 0 top
PP18  PROBE POINT  [PROBE_POINT_30PAD]  121.28 55.12 0 top
PP19  PROBE POINT  [PROBE_POINT_30PAD]  25.88 106.05 0 top
PP20  PROBE POINT  [PROBE_POINT_30PAD]  28.83 45.59 0 top
PP21  PROBE POINT  [PROBE_POINT_30PAD]  45.21 125.73 0 top
Q3  CSD18532Q5  [SON_Q5B_8]  24.89 27.43 180 bottom
R1  0  [0201]  31.42 107.47 270 top
R4  0  [0201]  32.43 107.47 270 top
R6  0  [0201]  31.43 84.05 90 top
R9  0  [0201]  32.43 84.05 90 top
R11  10k  [0402]  89.02 62.52 0 top
R12  10k  [0402]  89.02 61.38 0 top
R13  1k  [0402]  81.28 50.16 90 top
R14  1k  [0402]  83.82 50.16 90 top
R15  1k  [0402]  86.36 50.16 90 top
R16  1k  [0402]  88.9 50.16 90 top
R17  10k  [0402]  89.02 60.24 0 top
R18  10k  [0402]  89.02 59.09 0 top
R19  1k  [0402]  41.02 71.37 0 bottom
R20  1k  [0402]  37.47 126.24 90 bottom
R21  10k  [0402]  42.04 64.01 0 bottom
R22  0  [0201]  93.18 132.93 180 bottom
R23  10k  [0402]  37.47 123.7 270 bottom
R24  0  [0201]  93.18 133.69 180 bottom
R25  1k  [0402]  24.77 102.36 0 bottom
R26  2.1k  [0402]  26.42 102.87 90 bottom
R27  10k  [0402]  7.19 125.64 0 top
R28  10k  [0402]  13.97 127.25 180 top
R30  8.06k  [0402]  110.24 61.72 270 top
R31  1M  [0402]  100.08 59.56 270 top
R32  1.2k  [0402]  101.73 67.69 90 bottom
R33  1.33k  [0402]  112.52 61.72 90 top
R34  0  [0402]  11.81 65.53 0 top
R35  0  [0402]  12.32 65.02 90 top
R36  0  [0402]  12.32 62.99 270 top
R37  750  [0402]  13.97 128.4 180 top
R38  0  [0402]  11.81 62.48 0 top
R39  1.3k  [0402]  7.19 124.5 0 top
R40  0  [0402]  15.75 124.84 0 top
R41  1.3k  [0402]  7.19 123.35 0 top
R42  0  [0402]  15.75 126.11 0 top
R43  100  [0402]  20.7 95.76 90 top
R44  49.9  [0402]  56.87 138.88 90 bottom
R45  49.9  [0402]  56.87 136.85 270 bottom
R46  12k  [0402]  67.67 141.8 0 bottom
R47  100  [0402]  57.23 134.28 180 bottom
R48  49.9  [0402]  61.52 134.11 180 bottom
R49  49.9  [0402]  59.49 134.11 0 bottom
R50  680  [0201]  58.85 144.42 0 bottom
R51  680  [0201]  54.33 142.69 0 top
R52  49.9  [0201]  62.03 131.39 90 bottom
R53  49.9  [0201]  58.98 131.39 90 bottom
R54  0  [0201]  67.39 144.44 180 bottom
R55  12  [0201]  65.86 144.44 180 bottom
R56  150  [0201]  69.67 145.23 180 bottom
R57  240  [0201]  94.2 133.94 90 bottom
R58  240  [0201]  94.2 132.67 270 bottom
R59  0  [0201]  107.42 127.15 0 bottom
R60  0  [0201]  107.42 126.38 0 bottom
R61  240  [0201]  106.4 126.13 270 bottom
R62  240  [0201]  106.4 127.4 90 bottom
R63  39k  [0201]  93.96 116.4 180 bottom
R64  240  [0201]  106.4 128.62 270 bottom
R65  240  [0201]  106.4 129.89 90 bottom
R66  620  [0201]  88.62 129.36 90 bottom
R67  0  [0402]  79.48 120.21 270 bottom
R68  49.9  [0201]  88.5 121.36 270 bottom
R69  0  [0603]  83.67 120.72 0 bottom
R70  18  [0402]  76.68 120.72 0 bottom
R71  292  [0402]  75.03 120.21 270 bottom
R72  292  [0402]  78.34 120.21 270 bottom
R73  100  [0402]  87.35 121.99 90 bottom
R74  120  [0201]  105.29 117.75 0 bottom
R75  120  [0201]  104.02 117.75 180 bottom
R76  0  [0201]  107.58 118.9 270 bottom
R77  0  [0201]  106.81 118.9 270 bottom
R78  120  [0201]  107.83 119.91 0 bottom
R79  120  [0201]  106.56 119.91 180 bottom
R80  100  [0201]  106.56 117.88 180 bottom
R81  100  [0201]  107.83 117.88 0 bottom
R82  130  [0201]  86.97 125.9 90 bottom
R83  100  [0201]  84.56 126.18 0 bottom
R84  82  [0201]  83.54 125.93 270 bottom
R85  49.9  [0201]  87.73 125.9 270 bottom
R86  240  [0201]  96.37 131.26 180 bottom
R87  240  [0201]  97.64 131.26 0 bottom
R88  130  [0201]  86.97 127.17 270 bottom
R89  240  [0201]  100.39 133.73 180 bottom
R90  240  [0201]  101.66 133.73 0 bottom
R91  100  [0201]  84.56 126.94 0 bottom
R92  82  [0201]  83.54 127.2 90 bottom
R93  49.9  [0201]  87.73 127.17 90 bottom
R94  240  [0201]  97.18 118.18 0 bottom
R95  240  [0201]  95.81 118.18 180 bottom
R96  2.32k  [0402]  107.67 124.91 270 top
R97  0  [0402]  128.4 93.73 0 top
R98  0  [0402]  125.86 73.28 0 top
R99  10k  [0402]  105.26 126.44 0 top
R100  750  [0603]  50.87 141.68 0 bottom
R101  750  [0603]  50.87 138.88 0 bottom
R102  750  [0603]  50.87 144.47 0 bottom
R103  750  [0603]  50.87 136.09 0 bottom
R104  4.99k  [0402]  136.83 111.79 180 top
R105  0  [0402]  139.06 59.31 270 top
R106  100  [0603]  132.59 112.5 180 top
R107  0  [0402]  132.72 59.94 180 top
R108  100  [0201]  119.25 116.38 90 top
R109  270  [0402]  52.96 73 0 bottom
R110  100  [0402]  66.55 51.88 180 bottom
R111  0  [0603]  17.91 38.23 180 top
R112  100  [0402]  59.82 53.59 270 top
R113  100  [0402]  60.96 53.59 270 top
R114  10k  [0402]  68.45 63.75 180 top
R115  10k  [0402]  68.45 61.47 180 top
R116  10  [0603]  10.92 48.13 90 top
R117  10  [0603]  12.45 48.13 90 top
R118  100  [0402]  68.45 59.18 0 top
R119  100  [0402]  68.45 60.32 0 top
R120  100  [0402]  70.48 61.47 0 top
R121  100  [0402]  70.48 62.61 0 top
R122  12k  [0603]  55.25 62.87 180 bottom
R123  10k  [0402]  79.32 65.6 0 top
R124  10k  [0402]  74.87 67.84 0 top
R125  10k  [0402]  74.87 68.98 0 top
R126  0  [0201]  100.64 134.74 90 bottom
R127  0  [0201]  101.4 134.74 90 bottom
R128  0  [0201]  107.42 129.64 0 bottom
R129  0  [0201]  107.42 128.87 0 bottom
R130  1k  [0603]  51.77 58.84 0 top
R131  2.2k  [0603]  79.01 67.18 0 top
R132  10k  [0402]  49.4 39.24 0 bottom
R133  100  [0402]  52.83 40 0 top
R134  100  [0402]  52.83 38.86 0 top
R135  100  [0402]  52.83 37.72 0 top
R136  100  [0402]  52.83 36.58 0 top
R137  100  [0402]  52.83 35.43 0 top
R138  1k  [0402]  86.86 62.52 0 top
R139  1k  [0402]  86.86 61.38 0 top
R140  1k  [0402]  86.86 60.24 0 top
R141  1k  [0402]  86.86 59.09 0 top
R142  100  [0402]  86.86 57.95 0 top
R143  1k  [0402]  91.2 72.26 0 top
R144  1k  [0402]  91.2 71.12 0 top
R145  1k  [0402]  91.2 69.97 0 top
R146  1k  [0402]  91.2 68.83 0 top
R147  100  [0402]  91.2 67.69 0 top
R148  1K  [0402]  29.46 29.08 90 bottom
R151  0  [0201]  31.12 84.35 0 top
R162  0  [0201]  32.73 84.35 180 top
R178  100  [0402]  66.17 63.75 0 top
R179  0  [0201]  32.73 107.16 180 top
R180  0  [0201]  31.12 107.16 0 top
R184  1M  [0402]  110.87 58.29 270 top
R185  1.2k  [0402]  109.98 67.82 90 bottom
R186  0  [0201]  88.37 123.77 0 bottom
R187  51  [0201]  87.35 123.72 270 bottom
R188  240  [0201]  91.16 125.42 180 bottom
R189  240  [0201]  91.16 124.66 180 bottom
R190  49.9k  [0402]  60.45 16 180 top
R191  10k  [0402]  64.39 12.06 0 top
R193  28k  [0402]  41.02 14.1 0 top
R195  95.3k  [0402]  41.02 12.7 180 top
R196  9.31k  [0402]  38.35 13.97 0 top
R197  4.02k  [0805]  26.8 153.29 90 top
R198  6.81k  [0805]  26.8 149.48 90 top
R199  4.02k  [0805]  27.56 139.07 90 top
R200  6.81k  [0805]  27.56 135.26 90 top
R201  1.15k  [0402]  60.45 13.84 0 top
R202  10.7k  [0805]  64.77 10.41 0 top
R203  20k  [0402]  101.35 1.52 0 top
R204  8.25k  [0402]  79.38 3.05 270 top
R205  3.65k  [0402]  79.38 5.84 270 top
R206  8.45k  [0402]  98.55 11.05 180 top
R207  10k  [0402]  98.55 12.19 0 top
R210  49.9k  [0402]  60.45 32 180 top
R211  10k  [0402]  64.39 28.07 0 top
R212  28k  [0402]  41.02 30.1 0 top
R213  86.6k  [0402]  41.02 28.7 0 top
R214  9.31k  [0402]  41.02 31.37 180 top
R215  1.74k  [0402]  60.45 29.84 0 top
R216  20k  [0402]  100.33 22.99 0 top
R217  8.25k  [0402]  79.38 24.26 270 top
R218  3.65k  [0402]  79.38 27.05 270 top
R219  10k  [0402]  98.55 33.4 0 top
R220  21.5k  [0402]  98.55 32.26 180 top
R221  5.62k  [0805]  64.77 26.42 0 top
R222  0  [0805]  107.7 10.92 0 top
R223  0  [0402]  41.02 15.37 0 top
R224  0  [0402]  41.02 11.56 180 top
R225  100  [0402]  85.09 65.91 180 top
R226  100  [0402]  80.39 70.23 270 top
SJP1  SOLDER JUMPER, 0402  [SMD_JUMPER_L_0402]  79.73 145.87 270 top
SJP2  SOLDER JUMPER, 0402  [SJP2_JUMPER_0402]  55.5 35.43 0 top
SJP3  JUMPER_1X3_100  [JUMPER_SMD_3POS_0402]  50.93 52.83 270 top
SJP4  JUMPER_1X3_100  [JUMPER_SMD_3POS_0402]  52.58 52.83 270 top
SJP5  JUMPER_1X3_100  [JUMPER_SMD_3POS_0402]  54.23 52.83 270 top
SJP6  JUMPER_1X3_100  [JUMPER_SMD_3POS_0402]  56.01 52.83 270 top
SJP7  JUMPER_1X3_100  [JUMPER_SMD_3POS_0402]  69.6 52.7 270 top
SJP8  JUMPER_1X3_100  [JUMPER_SMD_3POS_0402]  71.12 52.7 270 top
SJP9  JUMPER_1X3_100  [JUMPER_SMD_3POS_0402]  72.64 52.7 270 top
SJP10  JUMPER_1X3_100  [JUMPER_SMD_3POS_0402]  74.17 52.7 270 top
SJP11  JUMPER_1X3_100  [JUMPER_SMD_3POS_0402]  71.12 49.02 270 top
SJP12  JUMPER_1X3_100  [JUMPER_SMD_3POS_0402]  69.6 49.02 270 top
SJP13  SOLDER JUMPER, 0402  [SJP2_JUMPER_0402]  93.85 67.69 0 top
SJP14  SOLDER JUMPER, 0402  [SJP2_JUMPER_0402]  91.95 57.94 0 top
SJP15  JUMPER_1X3_100  [JUMPER_SMD_3POS_0805]  79.07 42.67 180 top
SJP16  JUMPER_1X3_100  [JUMPER_SMD_3POS_0805]  89.89 43.31 180 top
SJP17  JUMPER_1X3_100  [JUMPER_SMD_3POS_0805]  78.23 14.81 180 top
T1  TC1-1-13M-23+  [TFMR_5_150X150_50]  83.54 121.99 0 bottom
T2  TC1-1-43X-4+  [TFMR_5_150X150_50]  17.27 95.76 0 top
TP1  ORN  [TP_THVT_100_RND]  3.3 129.41 0 top
TP2  ORN  [TP_THVT_100_RND]  3.3 125.6 0 top
TP4  ORN  [TP_THVT_100_RND]  113.41 73.91 0 top
TP5  GRN  [TP_THVT_100_RND]  77.72 52.07 0 top
TP6  BLK  [TP_THVT_100_RND]  105.79 17.14 0 top
TP7  BLK  [TP_THVT_100_RND]  70.61 149.99 0 top
TP8  BLK  [TP_THVT_100_RND]  21.62 14.1 0 top
TP9  ORN  [TP_THVT_100_RND]  14.48 119.38 0 top
TP10  ORN  [TP_THVT_100_RND]  18.29 119.38 0 top
TP11  BLK  [TP_THVT_100_RND]  3.3 121.79 0 top
TP12  RED  [TP_THVT_125_RND_063D]  23.37 41.27 0 top
TP13  BLK  [TP_THVT_125_RND_063D]  18.03 41.27 0 top
TP14  BLK  [TP_THVT_100_RND]  103.63 43.43 0 top
U1  ADC12DJ3200-CVAL  [BGA_196_1MM_VIA_IN_PAD]  34.93 95.76 270 top
U2  TMP461  [QFN_10_83X83_RUN]  11.25 125.39 180 top
U3  LMX2582  [QFN40_RTA_RTB_RHA]  62.05 139.36 180 bottom
U4  LMK04832  [WQFN_64_360X360_0P5MM_PWRPAD]  98.02 125.04 180 bottom
U5  24LC65  [SO_8_207X207_50]  119.13 62.74 270 top
U6  TLV70233  [SOT_5_120X69_37]  32 38.23 0 top
U7  SN74LVC1G125DBVR  [SOT_5_120X69_57]  65.53 52.83 270 top
U8  FT4232HQ  [QFN_64_0P50MM_RGC_FT2232HQ]  59.05 61.59 0 top
U9  93LC46B-I  [MSOP_8_118X118_0P65MM]  77.99 70.99 90 top
U10  SN74AVC4T774  [TSSOP_16_201X177_26]  46.41 37.72 0 top
U11  SN74AVC4T774  [TSSOP_16_201X177_26]  80.43 60.24 0 top
U12  SN74AVC4T774  [TSSOP_16_201X177_26]  84.77 69.97 0 top
U13  TPS2400  [DBV5]  23.37 35.43 90 top
U14  TPS50601A-SP  [CFP_20_300X510_50_PWRPAD]  50.93 25.53 0 top
U15  LMC6762  [SOIC_8_197X157_50]  105.54 60.71 0 top
U16  TPS7A4501-SP  [CFP_10_270X276_50_PWRPAD]  17.14 149.48 0 top
U17  TPS7A4501-SP  [CFP_10_270X276_50_PWRPAD]  17.91 135.26 0 top
U18  TPS50601A-SP  [CFP_20_300X510_50_PWRPAD]  50.93 9.53 0 top
U19  TPS7H1101A-SP  [DUAL_FLATPACK_TPS7H1101-SP]  88.65 6.73 0 top
U20  TPS7H1101A-SP  [DUAL_FLATPACK_TPS7H1101-SP]  88.65 27.94 0 top
Y1  100.00MHz  [VCXO_6_CUSTOM]  79.61 137.48 270 bottom
Y2  12MHz, 18pF  [XTAL_2_SM_126X197]  48.26 65.02 90 top

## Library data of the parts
BALUN1 BALUN2 = BALUN_MARKI_SMG_320x320
C1 C42 C172 C177 C190-C195 = CAP_0603_0.1uF
C2 C173 C175 C180 = CAP_0603_1uF
C3 C4 C14 C45 C47-C53 = CAP_0402_4700pF_H
C5-C13 C15 C16 C18 C19 C21-C23 C25-C40 C138 C144 C149 = CAP_0402_0.1uF_H: tolerance: 10%
C17 C123-C126 C129 C200 C202 C204 C218 C219 C222 C223 C229 C242 = CAP0201_0: tolerance: 20%
C20 C24 C100 C101 C103 C104 C106 C107 C109 C113 C133 C135 C142 C143 C146 C151 C153-C163 C165 C166 C249 C250 = CAPACITOR_NP_1: tolerance: 10%
C41 C44 = CAP_0603_100pF
C43 C68 C83 C95 = CAP_TANT_B_10uF_10V: tolerance: 20%
C54-C65 C69-C80 C84-C93 C96 C234 C245 C248 = CAP0402_0: tolerance: 10%
C66 C67 C81 C82 C94 C112 C115 C116 C118 C198 C201 C205 C220 C224 = CAP NP_1: tolerance: 10%
C99 C105 C108 C110 C139 = CAP_0603_100pF_H
C102 C111 C114 C117 C119-C122 C128 C130 C131 C145 C150 = CAP NP_0: tolerance: 10%
C127 C209 C231 C232 = CAP_0805_.1uF_25V
C132 = CAP NP_0: tolerance: 5%
C134 C136 = CAP_0402_0.01uF_H: tolerance: 10%
C137 = CAP_0402_0.1uF: tolerance: 10%
C140 = CAP_0402_2200pF_H
C141 = CAP_0402_10pF_H
C152 = CAPACITOR_NP_1: tolerance: 2%
C164 C168 C170 C179 = CAP_0603_10uF
C167 = CAP NP_1
C169 C171 C176 C181-C183 C186-C189 C215 C258 = CAP_0201_0.1uF
C174 C178 = CAP_1206_100uF_6.3V
C184 C185 = CAP_0402_18pF
C196 = CAP POL-B_0: tolerance: 10%
C203 C233 C237 C244 = CAP0603: tolerance: 10%
C206 C228 = CAP_TANT_D_220uF_6.3V: tolerance: 20%
C207 C226 = CAP_0805_1000pF_25V
C208 C227 = CAP_TANT_D_220uF_6.3V: tolerance: 10%
C210 C273 = CAP_0201_10000pF
C211 C272 = CAP_0201_2200pF
C212 C270 = CAP_1206_47uF
C213 C255 = CAP_1206_2.2uF
C214 C256 = CAP_0805_10uF_10V
C216 = CAP_0805_91pF_50V
C217 C254 = CAP_0805_9.0pF
C221 C251 = CAP_0805_0.1uF_X7R_50V
C225 C269 = CAP_0805_.027uF_50V
C230 C236 C243 C247 = CAP0201_0: tolerance: 10%
C259 C264 = CAP_0805_1uF_50V
C260 C265 = CAP_TANT_X_15uF_50V: tolerance: 20%
C261 C266 = CAP_0805_470pF
C262 C267 = CAP_TANT_D_22uF_25V: tolerance: 20%
C263 C268 = CAP_1210_.1uF_50V: tolerance: 10%, 50V, X7R
C271 = CAP_0805_130pF_50V
D1 = LED_RED_0
D2-D6 = LED
D7 D8 = LED_GREEN_0
D9 D12 = DIODE_1N4148W
D10 D11 = LED_ORANGE_0603
D13 = DIODE_MBRB2515L
F1 = FUSE_0
FB1-FB11 FB20-FB23 = FERRITE_BEAD_0402_H
FB12 FB13 = FERRITE_BEAD_0603_120_H
FB14 = FERRITE_BEAD_0603_26_H
FB16-FB19 FB24 FB25 = BEAD_NFM31P
J1 J3 J4 J6 J20 = SMP_PLUG_SMT_0
J2 J5 J23 J24 = SMA_THVT_SMA_CENTER_PIN
J7 = HEADER_2x4_100
J8 J9 J17 = HEADER_1x2_100
J14 J15 J18 = SMA_END_HIGH_FREQ_PSF-S01_0
J22 J38 = SMA-THVT_142-0701-201_REC_0
J25 = CON_SMVT_40X14_50_M
J26 J27 J30 = JUMPER_1X2_100
J28 = HEADER_1x4_100
J31 = USB_MINI_AB_MNE20-5G5P10
J37 = CONN JACK PWR
JP5 = HDR_2x1_100
JP6 = JUMPER_1X3_100
L6 L7 = IND_POWER_1.5uH
MT1 MT2 = MOUNTING_HOLE
PP1-PP21 = PROBE_POINT_0
Q3 = CSD18532Q5B
R1 R4 R6 R9 R151 R162 R179 R180 = Res_0201_Zero_H
R11 R12 R17 R18 R21 R23 R27 R28 R114 R115 R123-R125 R132 R207 R219 = Res_0402_10k
R13-R16 = Res_0402_1k_H
R19 R20 R25 = Res_0402_1k
R22 R24 R54 R59 R60 R76 R77 R126-R129 R186 = Res_0402_Zero_H_DNI
R26 = Res_0402_2.1K
R30 = Res_0402_8.06k
R31 R184 = Res_0402_1M
R32 R185 = Res_0402_1.2k
R33 = Res_0402_1.33k
R34-R36 R38 R40 R42 R97 R98 R223 R224 = Res_0402_Zero_H
R37 = Res_0603_750_H
R39 R41 = Res_0603_1.3k_H
R43 R47 R83 R91 R225 R226 = Res_0402_100_H
R44 R45 R48-R53 R68 = Res_0402_49.9
R46 R55 R70 = Res_0402_18
R56 R63 R66 = R_1
R57 R58 R61 R62 R64 R65 R74 R75 R78 R79 R86 R87 R89 R90 R94 R95 R188 R189 = Res_0402_249
R67 = R
R69 = Res_0603_Zero_DNI
R71 R72 R109 = Res_0402_270
R73 R80 R81 = Res_0603_100
R82 R100-R103 = RESISTOR_0
R84 R85 R88 R92 R93 = RESISTOR_0: tolerance: 1%
R96 = Res_0402_2.32K_H
R99 = Res_0402_1.3K
R104 = Res_0402_4.99K
R105 R107 = Res_0402_Zero
R106 R108 = Res_0201_100
R110 R112 R113 R118-R121 R133-R137 R142 R147 R178 = Res_0603_100_H
R111 = Res_0603_Zero
R116 R117 = Res_0603_10
R122 = Res_0603_12k
R130 R138-R141 R143-R146 = Res_0603_1k_H
R131 = Res_0603_2.2k
R148 = Res_0402_1k: tolerance: 1%
R187 = Res_0201_51_1%
R190 R210 = Res_0402_49.9k
R191 R211 = Res_0402_10k_H
R193 R212 = Res_0402_28k_H
R195 = Res_0402_95.3k
R196 R214 = Res_0402_9.31k_H
R197 R199 = Res_0805_4.02k
R198 R200 = Res_0805_6.81k
R201 = Res_0402_1.21k
R202 = Res_0402_9.76k
R203 R216 = Res_0402_20K_H
R204 R217 = Res_0402_8.25: tolerance: 1%
R205 R218 = Res_0402_3.65K_H
R206 = Res_0402_8.45k
R213 = Res_0402_86.6k_H
R215 = Res_0402_1.82k
R220 = Res_0402_21.5k
R221 = Res_0805_4.87k
R222 = Res_0805_Zero_H
SJP1 = SMD_JUMPER_1x3
SJP2 SJP13 SJP14 = JUMPER_SMD_1X2
SJP3-SJP12 SJP15-SJP17 = JUMPER_SMD_3POS_0402
T1 = TFMR_5_TC1-1-13M+
T2 = TFMR_5_TC1-1-43X+
TP1 TP2 TP9 TP10 = TESTPOINT_ORANGE
TP4 = TESTPOINT_BLUE
TP5 = TESTPOINT_GRN
TP6-TP8 TP11 TP14 = TESTPOINT_BLK
TP12 TP13 = TESTLOOP_BLACK
U1 = ADC12DJ1350_196PIN
U2 = TMP461
U3 = LMX2582_LM2592
U4 = LMK04828
U5 = 24LC65
U6 = TLV702
U7 = SN74LVC1G125DBVR
U8 = FT4232HQ
U9 = EEPROM_93LC46B
U10-U12 = SN74AVC4T774
U13 = TPS2400
U14 U18 = TPS50601A-SP
U15 = LMC6762
U16 U17 = TPS7A4501-SP
U19 U20 = TPS7H1101-SP
Y1 = OSC_SM_6_TCO-2100-SERIES_2
Y2 = CRYSTAL_ABM3_0

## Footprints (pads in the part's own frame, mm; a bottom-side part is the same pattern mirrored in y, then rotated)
0201
  rect 0.305x0.305 smd: 1(-0.305,0) 2(0.305,0)
0402
  rect 0.508x0.635 smd: 1(-0.508,0) 2(0.508,0)
0603
  rect 0.762x0.813 smd: 1(-0.787,0) 2(0.787,0)
0805
  rect 1.016x1.27 smd: 1(-1.016,0) 2(1.016,0)
1206
  rect 1.27x1.6 smd: 1(-1.524,0) 2(1.524,0)
1206_BEAD_NFM31P
  rect 1.016x1.575 smd: 1(-1.778,0) 3(1.778,0)
  rect 1.321x2.032 smd: 2(0,0)
1210
  rect 0.965x2.489 smd: 1(-1.372,0) 2(1.372,0)
BALUN_320X320_MARKI_0006SMG
  round 0.533 smd: 1(0,4.216) 2(1.524,-4.216) 3(-1.524,-4.216)
BGA_196_1MM_VIA_IN_PAD
  round 0.508 smd: A1(-6.5,-6.5) A2(-6.5,-5.5) A3(-6.5,-4.5) A4(-6.5,-3.5) A5(-6.5,-2.5) A6(-6.5,-1.5) A7(-6.5,-0.5) A8(-6.5,0.5) A9(-6.5,1.5) A10(-6.5,2.5) A11(-6.5,3.5) A12(-6.5,4.5) A13(-6.5,5.5) A14(-6.5,6.5) B1(-5.5,-6.5) B2(-5.5,-5.5) B3(-5.5,-4.5) B4(-5.5,-3.5) B5(-5.5,-2.5) B6(-5.5,-1.5) B7(-5.5,-0.5) B8(-5.5,0.5) B9(-5.5,1.5) B10(-5.5,2.5) B11(-5.5,3.5) B12(-5.5,4.5) B13(-5.5,5.5) B14(-5.5,6.5) C1(-4.5,-6.5) C2(-4.5,-5.5) C3(-4.5,-4.5) C4(-4.5,-3.5) C5(-4.5,-2.5) C6(-4.5,-1.5) C7(-4.5,-0.5) C8(-4.5,0.5) C9(-4.5,1.5) C10(-4.5,2.5) C11(-4.5,3.5) C12(-4.5,4.5) C13(-4.5,5.5) C14(-4.5,6.5) D1(-3.5,-6.5) D2(-3.5,-5.5) D3(-3.5,-4.5) D4(-3.5,-3.5) D5(-3.5,-2.5) D6(-3.5,-1.5) D7(-3.5,-0.5) D8(-3.5,0.5) D9(-3.5,1.5) D10(-3.5,2.5) D11(-3.5,3.5) D12(-3.5,4.5) D13(-3.5,5.5) D14(-3.5,6.5) E1(-2.5,-6.5) E2(-2.5,-5.5) E3(-2.5,-4.5) E4(-2.5,-3.5) E5(-2.5,-2.5) E6(-2.5,-1.5) E7(-2.5,-0.5) E8(-2.5,0.5) E9(-2.5,1.5) E10(-2.5,2.5) E11(-2.5,3.5) E12(-2.5,4.5) E13(-2.5,5.5) E14(-2.5,6.5) F1(-1.5,-6.5) F2(-1.5,-5.5) F3(-1.5,-4.5) F4(-1.5,-3.5) F5(-1.5,-2.5) F6(-1.5,-1.5) F7(-1.5,-0.5) F8(-1.5,0.5) F9(-1.5,1.5) F10(-1.5,2.5) F11(-1.5,3.5) F12(-1.5,4.5) F13(-1.5,5.5) F14(-1.5,6.5) G1(-0.5,-6.5) G2(-0.5,-5.5) G3(-0.5,-4.5) G4(-0.5,-3.5) G5(-0.5,-2.5) G6(-0.5,-1.5) G7(-0.5,-0.5) G8(-0.5,0.5) G9(-0.5,1.5) G10(-0.5,2.5) G11(-0.5,3.5) G12(-0.5,4.5) G13(-0.5,5.5) G14(-0.5,6.5) H1(0.5,-6.5) H2(0.5,-5.5) H3(0.5,-4.5) H4(0.5,-3.5) H5(0.5,-2.5) H6(0.5,-1.5) H7(0.5,-0.5) H8(0.5,0.5) H9(0.5,1.5) H10(0.5,2.5) H11(0.5,3.5) H12(0.5,4.5) H13(0.5,5.5) H14(0.5,6.5) J1(1.5,-6.5) J2(1.5,-5.5) J3(1.5,-4.5) J4(1.5,-3.5) J5(1.5,-2.5) J6(1.5,-1.5) J7(1.5,-0.5) J8(1.5,0.5) J9(1.5,1.5) J10(1.5,2.5) J11(1.5,3.5) J12(1.5,4.5) J13(1.5,5.5) J14(1.5,6.5) K1(2.5,-6.5) K2(2.5,-5.5) K3(2.5,-4.5) K4(2.5,-3.5) K5(2.5,-2.5) K6(2.5,-1.5) K7(2.5,-0.5) K8(2.5,0.5) K9(2.5,1.5) K10(2.5,2.5) K11(2.5,3.5) K12(2.5,4.5) K13(2.5,5.5) K14(2.5,6.5) L1(3.5,-6.5) L2(3.5,-5.5) L3(3.5,-4.5) L4(3.5,-3.5) L5(3.5,-2.5) L6(3.5,-1.5) L7(3.5,-0.5) L8(3.5,0.5) L9(3.5,1.5) L10(3.5,2.5) L11(3.5,3.5) L12(3.5,4.5) L13(3.5,5.5) L14(3.5,6.5) M1(4.5,-6.5) M2(4.5,-5.5) M3(4.5,-4.5) M4(4.5,-3.5) M5(4.5,-2.5) M6(4.5,-1.5) M7(4.5,-0.5) M8(4.5,0.5) M9(4.5,1.5) M10(4.5,2.5) M11(4.5,3.5) M12(4.5,4.5) M13(4.5,5.5) M14(4.5,6.5) N1(5.5,-6.5) N2(5.5,-5.5) N3(5.5,-4.5) N4(5.5,-3.5) N5(5.5,-2.5) N6(5.5,-1.5) N7(5.5,-0.5) N8(5.5,0.5) N9(5.5,1.5) N10(5.5,2.5) N11(5.5,3.5) N12(5.5,4.5) N13(5.5,5.5) N14(5.5,6.5) P1(6.5,-6.5) P2(6.5,-5.5) P3(6.5,-4.5) P4(6.5,-3.5) P5(6.5,-2.5) P6(6.5,-1.5) P7(6.5,-0.5) P8(6.5,0.5) P9(6.5,1.5) P10(6.5,2.5) P11(6.5,3.5) P12(6.5,4.5) P13(6.5,5.5) P14(6.5,6.5)
CFP_10_270X276_50_PWRPAD
  rect 1.422x0.551 smd: 1(-5.893,2.54) 2(-5.893,1.27) 3(-5.893,0) 4(-5.893,-1.27) 5(-5.893,-2.54) 6(5.893,-2.54) 7(5.893,-1.27) 8(5.893,0) 9(5.893,1.27) 10(5.893,2.54)
  rect 4.318x6.604 smd: 11(0,0)
CFP_20_300X510_50_PWRPAD
  rect 1.422x0.551 smd: 1(-7.061,5.715) 2(-7.061,4.445) 3(-7.061,3.175) 4(-7.061,1.905) 5(-7.061,0.635) 6(-7.061,-0.635) 7(-7.074,-1.905) 8(-7.074,-3.175) 9(-7.074,-4.445) 10(-7.074,-5.715) 11(7.061,-5.715) 12(7.061,-4.445) 13(7.061,-3.175) 14(7.061,-1.905) 15(7.061,-0.635) 16(7.061,0.635) 17(7.061,1.905) 18(7.061,3.175) 19(7.061,4.445) 20(7.061,5.715)
  rect 4.318x8.89 smd: 21(0,0)
CON_RAPC722_JACK_THVT_3
  round 4.318 hole 3.556: 1(0,3.124)
  round 3.81 hole 3.048: 2(0,-3.124) 3(4.801,0.127)
CON_SMRT_USBMNE20_F
  round 0.025 hole 0.991 unplated: (0.65,2.2) (0.65,-2.2)
  rect 2.311x0.508 smd: 1(3.45,1.6) 2(3.45,0.8) 3(3.45,0) 4(3.45,-0.8) 5(3.45,-1.6)
  rect 2.489x2.007 smd: 6(-2.15,-4.45) 7(3.35,-4.45) 8(3.35,4.45) 9(-2.15,4.45)
CON_SMVT_40X14_50_M_MTG
  round 3.81 hole 2.692: (-31.496,-2.007) (31.496,-2.007)
  round 1.27 hole 1.27 unplated: (-27.191,-3.048) (27.191,0)
  round 0.635 smd: A1(24.765,5.715) A2(23.495,5.715) A3(22.225,5.715) A4(20.955,5.715) A5(19.685,5.715) A6(18.415,5.715) A7(17.145,5.715) A8(15.875,5.715) A9(14.605,5.715) A10(13.335,5.715) A11(12.065,5.715) A12(10.795,5.715) A13(9.525,5.715) A14(8.255,5.715) A15(6.985,5.715) A16(5.715,5.715) A17(4.445,5.715) A18(3.175,5.715) A19(1.905,5.715) A20(0.635,5.715) A21(-0.635,5.715) A22(-1.905,5.715) A23(-3.175,5.715) A24(-4.445,5.715) A25(-5.715,5.715) A26(-6.985,5.715) A27(-8.255,5.715) A28(-9.525,5.715) A29(-10.795,5.715) A30(-12.065,5.715) A31(-13.335,5.715) A32(-14.605,5.715) A33(-15.875,5.715) A34(-17.145,5.715) A35(-18.415,5.715) A36(-19.685,5.715) A37(-20.955,5.715) A38(-22.225,5.715) A39(-23.495,5.715) A40(-24.765,5.715) B1(24.765,4.445) B2(23.495,4.445) B3(22.225,4.445) B4(20.955,4.445) B5(19.685,4.445) B6(18.415,4.445) B7(17.145,4.445) B8(15.875,4.445) B9(14.605,4.445) B10(13.335,4.445) B11(12.065,4.445) B12(10.795,4.445) B13(9.525,4.445) B14(8.255,4.445) B15(6.985,4.445) B16(5.715,4.445) B17(4.445,4.445) B18(3.175,4.445) B19(1.905,4.445) B20(0.635,4.445) B21(-0.635,4.445) B22(-1.905,4.445) B23(-3.175,4.445) B24(-4.445,4.445) B25(-5.715,4.445) B26(-6.985,4.445) B27(-8.255,4.445) B28(-9.525,4.445) B29(-10.795,4.445) B30(-12.065,4.445) B31(-13.335,4.445) B32(-14.605,4.445) B33(-15.875,4.445) B34(-17.145,4.445) B35(-18.415,4.445) B36(-19.685,4.445) B37(-20.955,4.445) B38(-22.225,4.445) B39(-23.495,4.445) B40(-24.765,4.445) C1(24.765,3.175) C2(23.495,3.175) C3(22.225,3.175) C4(20.955,3.175) C5(19.685,3.175) C6(18.415,3.175) C7(17.145,3.175) C8(15.875,3.175) C9(14.605,3.175) C10(13.335,3.175) C11(12.065,3.175) C12(10.795,3.175) C13(9.525,3.175) C14(8.255,3.175) C15(6.985,3.175) C16(5.715,3.175) C17(4.445,3.175) C18(3.175,3.175) C19(1.905,3.175) C20(0.635,3.175) C21(-0.635,3.175) C22(-1.905,3.175) C23(-3.175,3.175) C24(-4.445,3.175) C25(-5.715,3.175) C26(-6.985,3.175) C27(-8.255,3.175) C28(-9.525,3.175) C29(-10.795,3.175) C30(-12.065,3.175) C31(-13.335,3.175) C32(-14.605,3.175) C33(-15.875,3.175) C34(-17.145,3.175) C35(-18.415,3.175) C36(-19.685,3.175) C37(-20.955,3.175) C38(-22.225,3.175) C39(-23.495,3.175) C40(-24.765,3.175) D1(24.765,1.905) D2(23.495,1.905) D3(22.225,1.905) D4(20.955,1.905) D5(19.685,1.905) D6(18.415,1.905) D7(17.145,1.905) D8(15.875,1.905) D9(14.605,1.905) D10(13.335,1.905) D11(12.065,1.905) D12(10.795,1.905) D13(9.525,1.905) D14(8.255,1.905) D15(6.985,1.905) D16(5.715,1.905) D17(4.445,1.905) D18(3.175,1.905) D19(1.905,1.905) D20(0.635,1.905) D21(-0.635,1.905) D22(-1.905,1.905) D23(-3.175,1.905) D24(-4.445,1.905) D25(-5.715,1.905) D26(-6.985,1.905) D27(-8.255,1.905) D28(-9.525,1.905) D29(-10.795,1.905) D30(-12.065,1.905) D31(-13.335,1.905) D32(-14.605,1.905) D33(-15.875,1.905) D34(-17.145,1.905) D35(-18.415,1.905) D36(-19.685,1.905) D37(-20.955,1.905) D38(-22.225,1.905) D39(-23.495,1.905) D40(-24.765,1.905) E1(24.765,0.635) E2(23.495,0.635) E3(22.225,0.635) E4(20.955,0.635) E5(19.685,0.635) E6(18.415,0.635) E7(17.145,0.635) E8(15.875,0.635) E9(14.605,0.635) E10(13.335,0.635) E11(12.065,0.635) E12(10.795,0.635) E13(9.525,0.635) E14(8.255,0.635) E15(6.985,0.635) E16(5.715,0.635) E17(4.445,0.635) E18(3.175,0.635) E19(1.905,0.635) E20(0.635,0.635) E21(-0.635,0.635) E22(-1.905,0.635) E23(-3.175,0.635) E24(-4.445,0.635) E25(-5.715,0.635) E26(-6.985,0.635) E27(-8.255,0.635) E28(-9.525,0.635) E29(-10.795,0.635) E30(-12.065,0.635) E31(-13.335,0.635) E32(-14.605,0.635) E33(-15.875,0.635) E34(-17.145,0.635) E35(-18.415,0.635) E36(-19.685,0.635) E37(-20.955,0.635) E38(-22.225,0.635) E39(-23.495,0.635) E40(-24.765,0.635) F1(24.765,-0.635) F2(23.495,-0.635) F3(22.225,-0.635) F4(20.955,-0.635) F5(19.685,-0.635) F6(18.415,-0.635) F7(17.145,-0.635) F8(15.875,-0.635) F9(14.605,-0.635) F10(13.335,-0.635) F11(12.065,-0.635) F12(10.795,-0.635) F13(9.525,-0.635) F14(8.255,-0.635) F15(6.985,-0.635) F16(5.715,-0.635) F17(4.445,-0.635) F18(3.175,-0.635) F19(1.905,-0.635) F20(0.635,-0.635) F21(-0.635,-0.635) F22(-1.905,-0.635) F23(-3.175,-0.635) F24(-4.445,-0.635) F25(-5.715,-0.635) F26(-6.985,-0.635) F27(-8.255,-0.635) F28(-9.525,-0.635) F29(-10.795,-0.635) F30(-12.065,-0.635) F31(-13.335,-0.635) F32(-14.605,-0.635) F33(-15.875,-0.635) F34(-17.145,-0.635) F35(-18.415,-0.635) F36(-19.685,-0.635) F37(-20.955,-0.635) F38(-22.225,-0.635) F39(-23.495,-0.635) F40(-24.765,-0.635) G1(24.765,-1.905) G2(23.495,-1.905) G3(22.225,-1.905) G4(20.955,-1.905) G5(19.685,-1.905) G6(18.415,-1.905) G7(17.145,-1.905) G8(15.875,-1.905) G9(14.605,-1.905) G10(13.335,-1.905) G11(12.065,-1.905) G12(10.795,-1.905) G13(9.525,-1.905) G14(8.255,-1.905) G15(6.985,-1.905) G16(5.715,-1.905) G17(4.445,-1.905) G18(3.175,-1.905) G19(1.905,-1.905) G20(0.635,-1.905) G21(-0.635,-1.905) G22(-1.905,-1.905) G23(-3.175,-1.905) G24(-4.445,-1.905) G25(-5.715,-1.905) G26(-6.985,-1.905) G27(-8.255,-1.905) G28(-9.525,-1.905) G29(-10.795,-1.905) G30(-12.065,-1.905) G31(-13.335,-1.905) G32(-14.605,-1.905) G33(-15.875,-1.905) G34(-17.145,-1.905) G35(-18.415,-1.905) G36(-19.685,-1.905) G37(-20.955,-1.905) G38(-22.225,-1.905) G39(-23.495,-1.905) G40(-24.765,-1.905) H1(24.765,-3.175) H2(23.495,-3.175) H3(22.225,-3.175) H4(20.955,-3.175) H5(19.685,-3.175) H6(18.415,-3.175) H7(17.145,-3.175) H8(15.875,-3.175) H9(14.605,-3.175) H10(13.335,-3.175) H11(12.065,-3.175) H12(10.795,-3.175) H13(9.525,-3.175) H14(8.255,-3.175) H15(6.985,-3.175) H16(5.715,-3.175) H17(4.445,-3.175) H18(3.175,-3.175) H19(1.905,-3.175) H20(0.635,-3.175) H21(-0.635,-3.175) H22(-1.905,-3.175) H23(-3.175,-3.175) H24(-4.445,-3.175) H25(-5.715,-3.175) H26(-6.985,-3.175) H27(-8.255,-3.175) H28(-9.525,-3.175) H29(-10.795,-3.175) H30(-12.065,-3.175) H31(-13.335,-3.175) H32(-14.605,-3.175) H33(-15.875,-3.175) H34(-17.145,-3.175) H35(-18.415,-3.175) H36(-19.685,-3.175) H37(-20.955,-3.175) H38(-22.225,-3.175) H39(-23.495,-3.175) H40(-24.765,-3.175) J1(24.765,-4.445) J2(23.495,-4.445) J3(22.225,-4.445) J4(20.955,-4.445) J5(19.685,-4.445) J6(18.415,-4.445) J7(17.145,-4.445) J8(15.875,-4.445) J9(14.605,-4.445) J10(13.335,-4.445) J11(12.065,-4.445) J12(10.795,-4.445) J13(9.525,-4.445) J14(8.255,-4.445) J15(6.985,-4.445) J16(5.715,-4.445) J17(4.445,-4.445) J18(3.175,-4.445) J19(1.905,-4.445) J20(0.635,-4.445) J21(-0.635,-4.445) J22(-1.905,-4.445) J23(-3.175,-4.445) J24(-4.445,-4.445) J25(-5.715,-4.445) J26(-6.985,-4.445) J27(-8.255,-4.445) J28(-9.525,-4.445) J29(-10.795,-4.445) J30(-12.065,-4.445) J31(-13.335,-4.445) J32(-14.605,-4.445) J33(-15.875,-4.445) J34(-17.145,-4.445) J35(-18.415,-4.445) J36(-19.685,-4.445) J37(-20.955,-4.445) J38(-22.225,-4.445) J39(-23.495,-4.445) J40(-24.765,-4.445) K1(24.765,-5.715) K2(23.495,-5.715) K3(22.225,-5.715) K4(20.955,-5.715) K5(19.685,-5.715) K6(18.415,-5.715) K7(17.145,-5.715) K8(15.875,-5.715) K9(14.605,-5.715) K10(13.335,-5.715) K11(12.065,-5.715) K12(10.795,-5.715) K13(9.525,-5.715) K14(8.255,-5.715) K15(6.985,-5.715) K16(5.715,-5.715) K17(4.445,-5.715) K18(3.175,-5.715) K19(1.905,-5.715) K20(0.635,-5.715) K21(-0.635,-5.715) K22(-1.905,-5.715) K23(-3.175,-5.715) K24(-4.445,-5.715) K25(-5.715,-5.715) K26(-6.985,-5.715) K27(-8.255,-5.715) K28(-9.525,-5.715) K29(-10.795,-5.715) K30(-12.065,-5.715) K31(-13.335,-5.715) K32(-14.605,-5.715) K33(-15.875,-5.715) K34(-17.145,-5.715) K35(-18.415,-5.715) K36(-19.685,-5.715) K37(-20.955,-5.715) K38(-22.225,-5.715) K39(-23.495,-5.715) K40(-24.765,-5.715) L1(24.765,-6.985) L2(23.495,-6.985) L3(22.225,-6.985) L4(20.955,-6.985) L5(19.685,-6.985) L6(18.415,-6.985) L7(17.145,-6.985) L8(15.875,-6.985) L9(14.605,-6.985) L10(13.335,-6.985) L11(12.065,-6.985) L12(10.795,-6.985) L13(9.525,-6.985) L14(8.255,-6.985) L15(6.985,-6.985) L16(5.715,-6.985) L17(4.445,-6.985) L18(3.175,-6.985) L19(1.905,-6.985) L20(0.635,-6.985) L21(-0.635,-6.985) L22(-1.905,-6.985) L23(-3.175,-6.985) L24(-4.445,-6.985) L25(-5.715,-6.985) L26(-6.985,-6.985) L27(-8.255,-6.985) L28(-9.525,-6.985) L29(-10.795,-6.985) L30(-12.065,-6.985) L31(-13.335,-6.985) L32(-14.605,-6.985) L33(-15.875,-6.985) L34(-17.145,-6.985) L35(-18.415,-6.985) L36(-19.685,-6.985) L37(-20.955,-6.985) L38(-22.225,-6.985) L39(-23.495,-6.985) L40(-24.765,-6.985) M1(24.765,-8.255) M2(23.495,-8.255) M3(22.225,-8.255) M4(20.955,-8.255) M5(19.685,-8.255) M6(18.415,-8.255) M7(17.145,-8.255) M8(15.875,-8.255) M9(14.605,-8.255) M10(13.335,-8.255) M11(12.065,-8.255) M12(10.795,-8.255) M13(9.525,-8.255) M14(8.255,-8.255) M15(6.985,-8.255) M16(5.715,-8.255) M17(4.445,-8.255) M18(3.175,-8.255) M19(1.905,-8.255) M20(0.635,-8.255) M21(-0.635,-8.255) M22(-1.905,-8.255) M23(-3.175,-8.255) M24(-4.445,-8.255) M25(-5.715,-8.255) M26(-6.985,-8.255) M27(-8.255,-8.255) M28(-9.525,-8.255) M29(-10.795,-8.255) M30(-12.065,-8.255) M31(-13.335,-8.255) M32(-14.605,-8.255) M33(-15.875,-8.255) M34(-17.145,-8.255) M35(-18.415,-8.255) M36(-19.685,-8.255) M37(-20.955,-8.255) M38(-22.225,-8.255) M39(-23.495,-8.255) M40(-24.765,-8.255) Y1(24.765,8.255) Y2(23.495,8.255) Y3(22.225,8.255) Y4(20.955,8.255) Y5(19.685,8.255) Y6(18.415,8.255) Y7(17.145,8.255) Y8(15.875,8.255) Y9(14.605,8.255) Y10(13.335,8.255) Y11(12.065,8.255) Y12(10.795,8.255) Y13(9.525,8.255) Y14(8.255,8.255) Y15(6.985,8.255) Y16(5.715,8.255) Y17(4.445,8.255) Y18(3.175,8.255) Y19(1.905,8.255) Y20(0.635,8.255) Y21(-0.635,8.255) Y22(-1.905,8.255) Y23(-3.175,8.255) Y24(-4.445,8.255) Y25(-5.715,8.255) Y26(-6.985,8.255) Y27(-8.255,8.255) Y28(-9.525,8.255) Y29(-10.795,8.255) Y30(-12.065,8.255) Y31(-13.335,8.255) Y32(-14.605,8.255) Y33(-15.875,8.255) Y34(-17.145,8.255) Y35(-18.415,8.255) Y36(-19.685,8.255) Y37(-20.955,8.255) Y38(-22.225,8.255) Y39(-23.495,8.255) Y40(-24.765,8.255) Z1(24.765,6.985) Z2(23.495,6.985) Z3(22.225,6.985) Z4(20.955,6.985) Z5(19.685,6.985) Z6(18.415,6.985) Z7(17.145,6.985) Z8(15.875,6.985) Z9(14.605,6.985) Z10(13.335,6.985) Z11(12.065,6.985) Z12(10.795,6.985) Z13(9.525,6.985) Z14(8.255,6.985) Z15(6.985,6.985) Z16(5.715,6.985) Z17(4.445,6.985) Z18(3.175,6.985) Z19(1.905,6.985) Z20(0.635,6.985) Z21(-0.635,6.985) Z22(-1.905,6.985) Z23(-3.175,6.985) Z24(-4.445,6.985) Z25(-5.715,6.985) Z26(-6.985,6.985) Z27(-8.255,6.985) Z28(-9.525,6.985) Z29(-10.795,6.985) Z30(-12.065,6.985) Z31(-13.335,6.985) Z32(-14.605,6.985) Z33(-15.875,6.985) Z34(-17.145,6.985) Z35(-18.415,6.985) Z36(-19.685,6.985) Z37(-20.955,6.985) Z38(-22.225,6.985) Z39(-23.495,6.985) Z40(-24.765,6.985)
